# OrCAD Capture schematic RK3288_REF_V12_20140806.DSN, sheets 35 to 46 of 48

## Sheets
35 72.Audio Codec-ALC3224 (option): size A3; title: Audio Codec-ALC3224 (option); note: Audio Codec-ALC3224
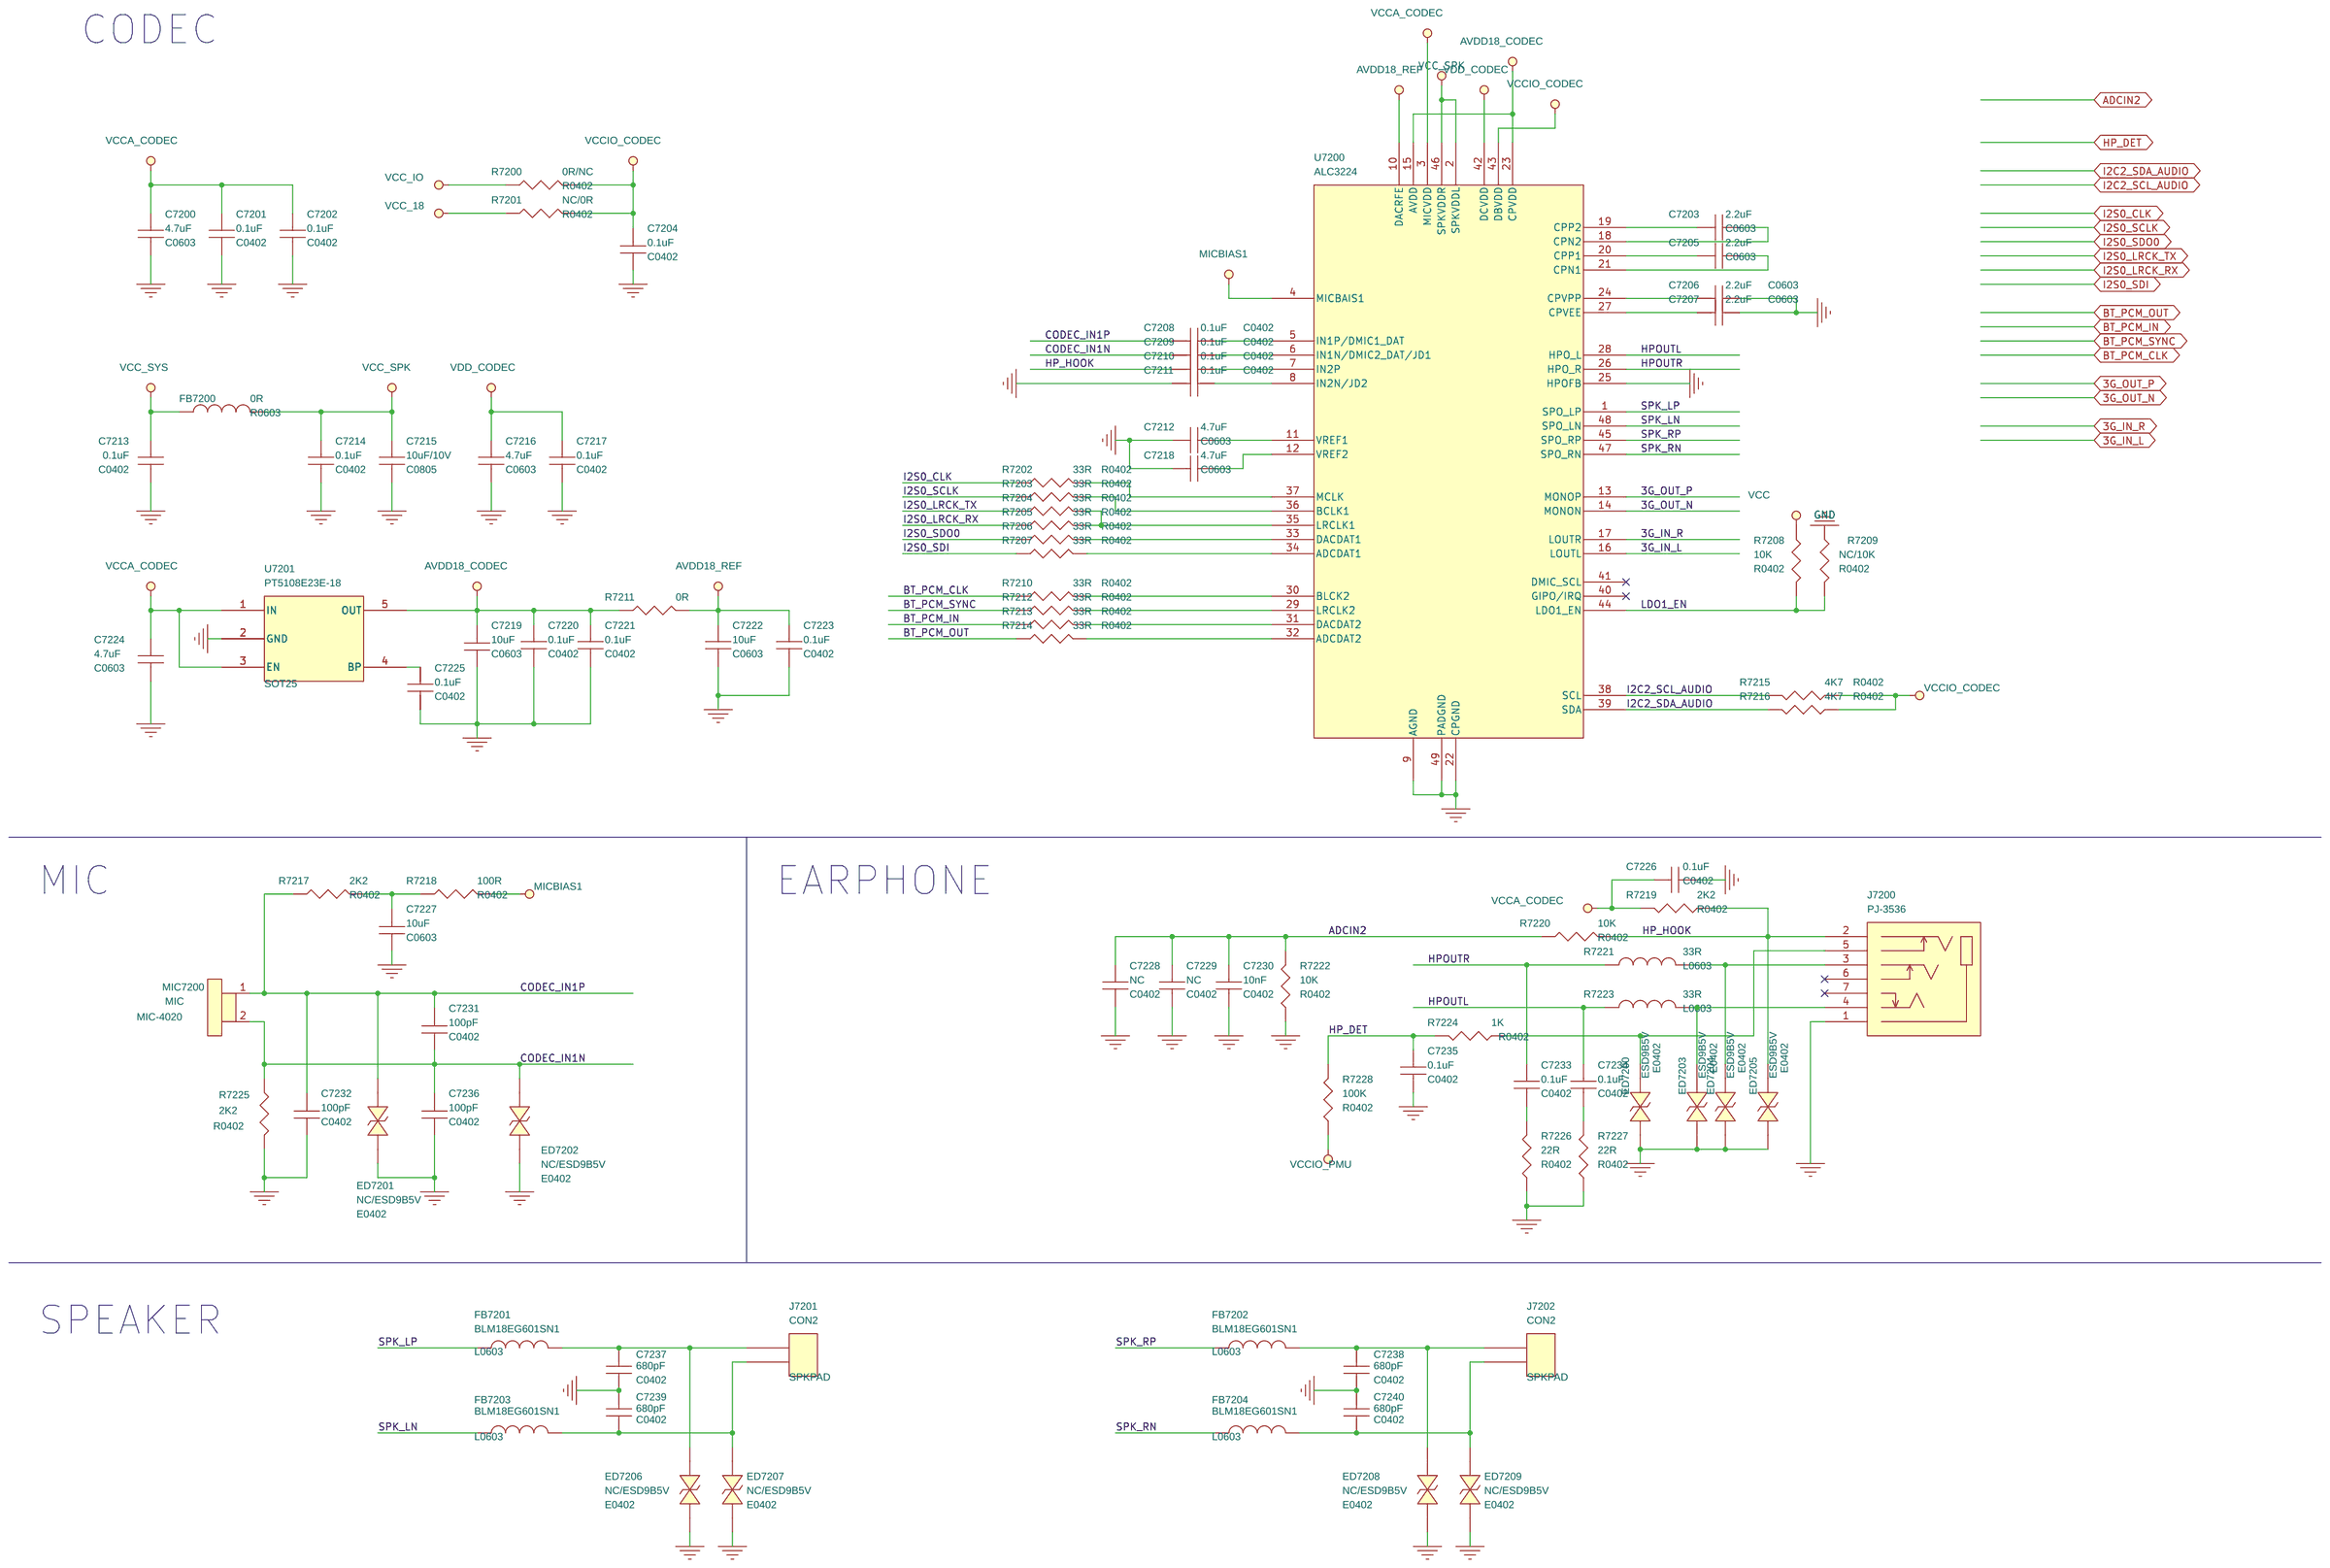
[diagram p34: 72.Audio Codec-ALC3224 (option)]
36 75.TP COF: size A4; title: TP COF; note: TP COF
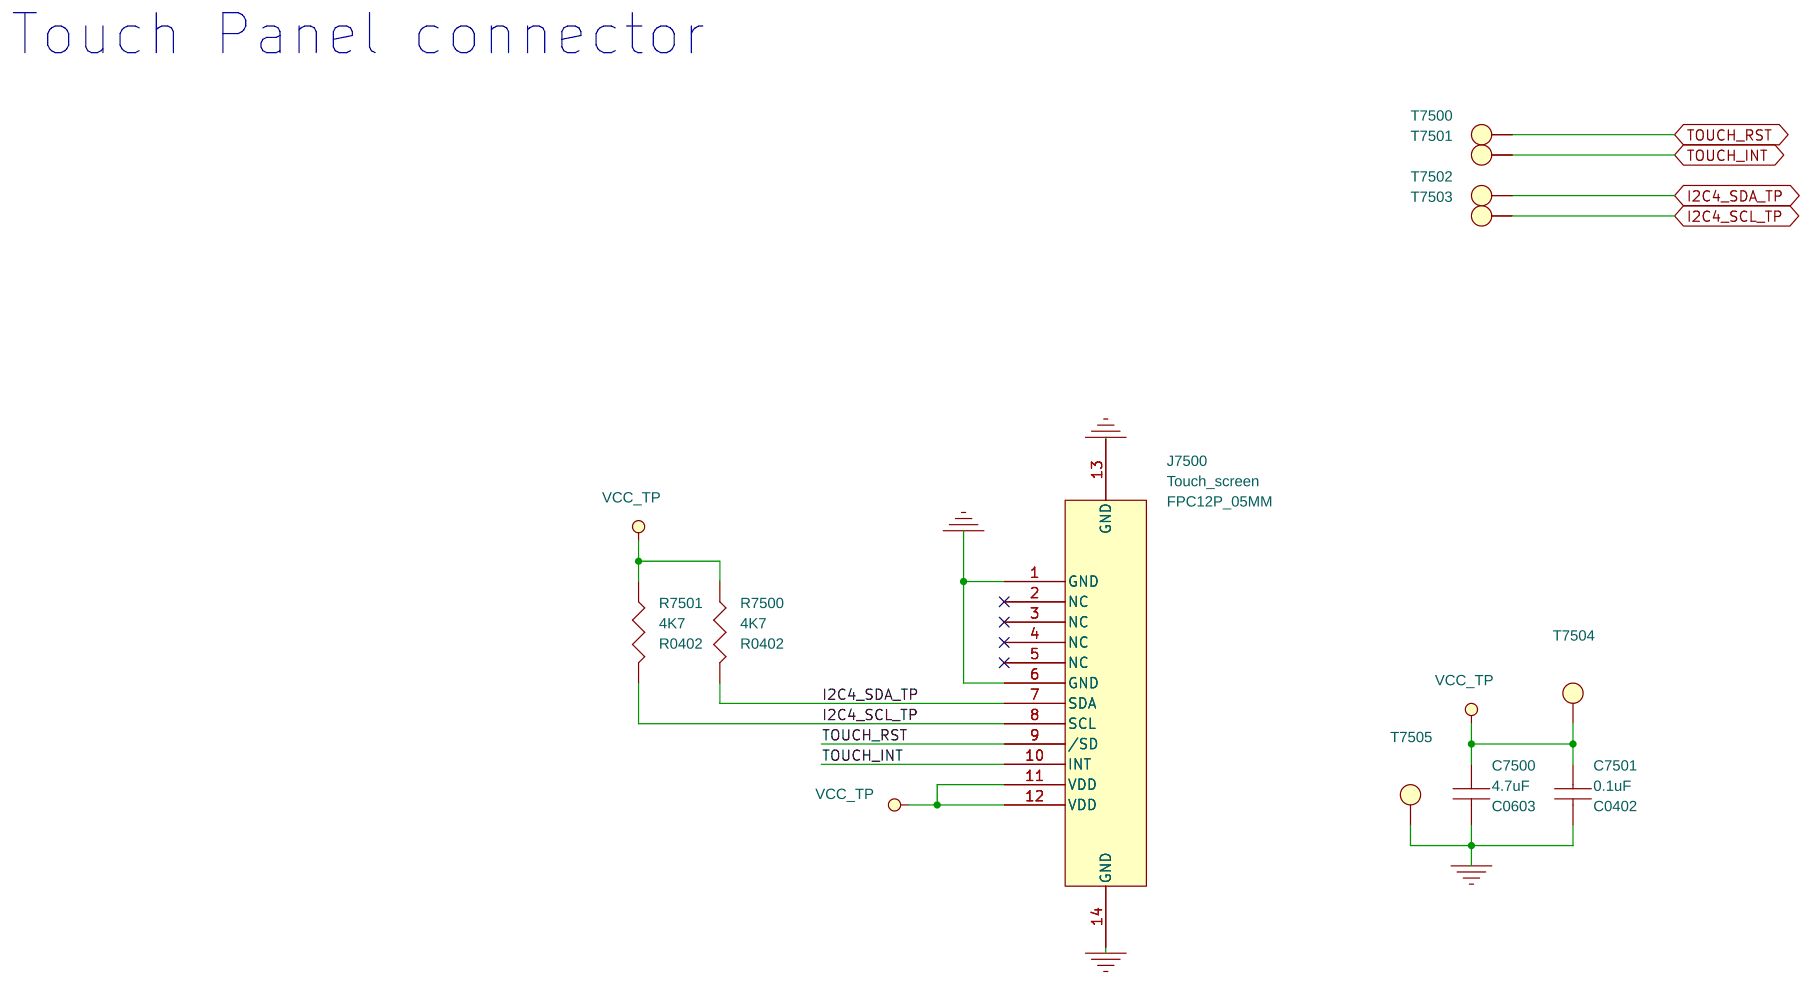
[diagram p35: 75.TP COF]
37 76.TP COB-CT363 (option): size A4; title: TP COB-CT363 (option); note: TP COB-CT363 (option)
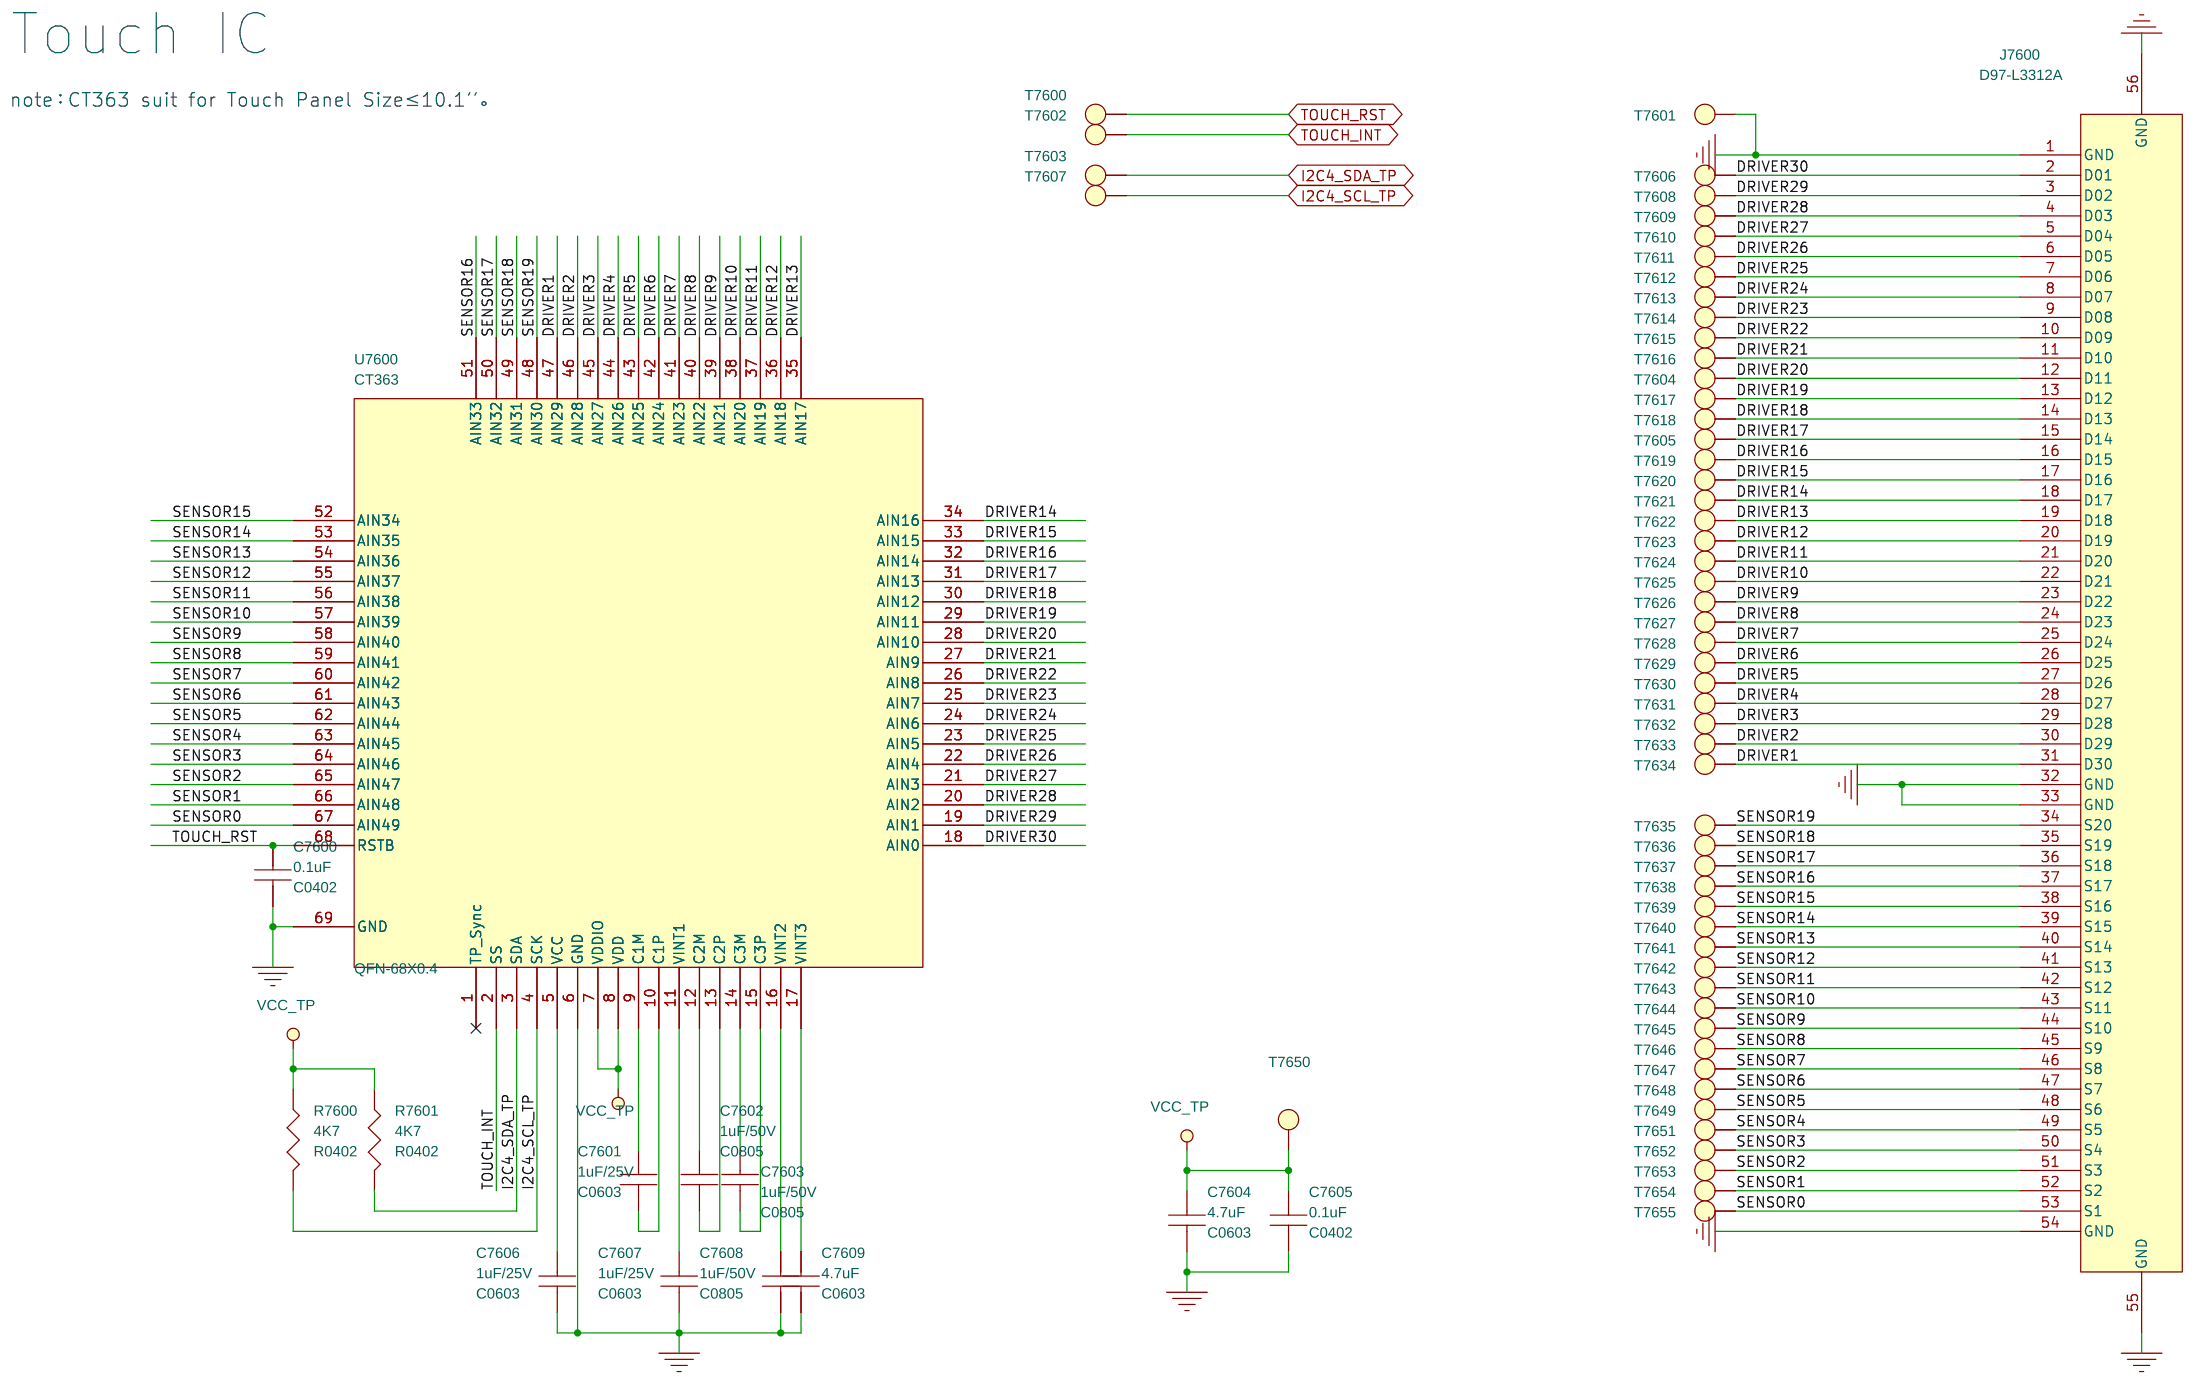
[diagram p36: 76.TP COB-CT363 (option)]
38 77.TP COB-FT5506 (option): size A4; title: TP COB-FT5506 (option); note: TP COB-FT5506 (option)
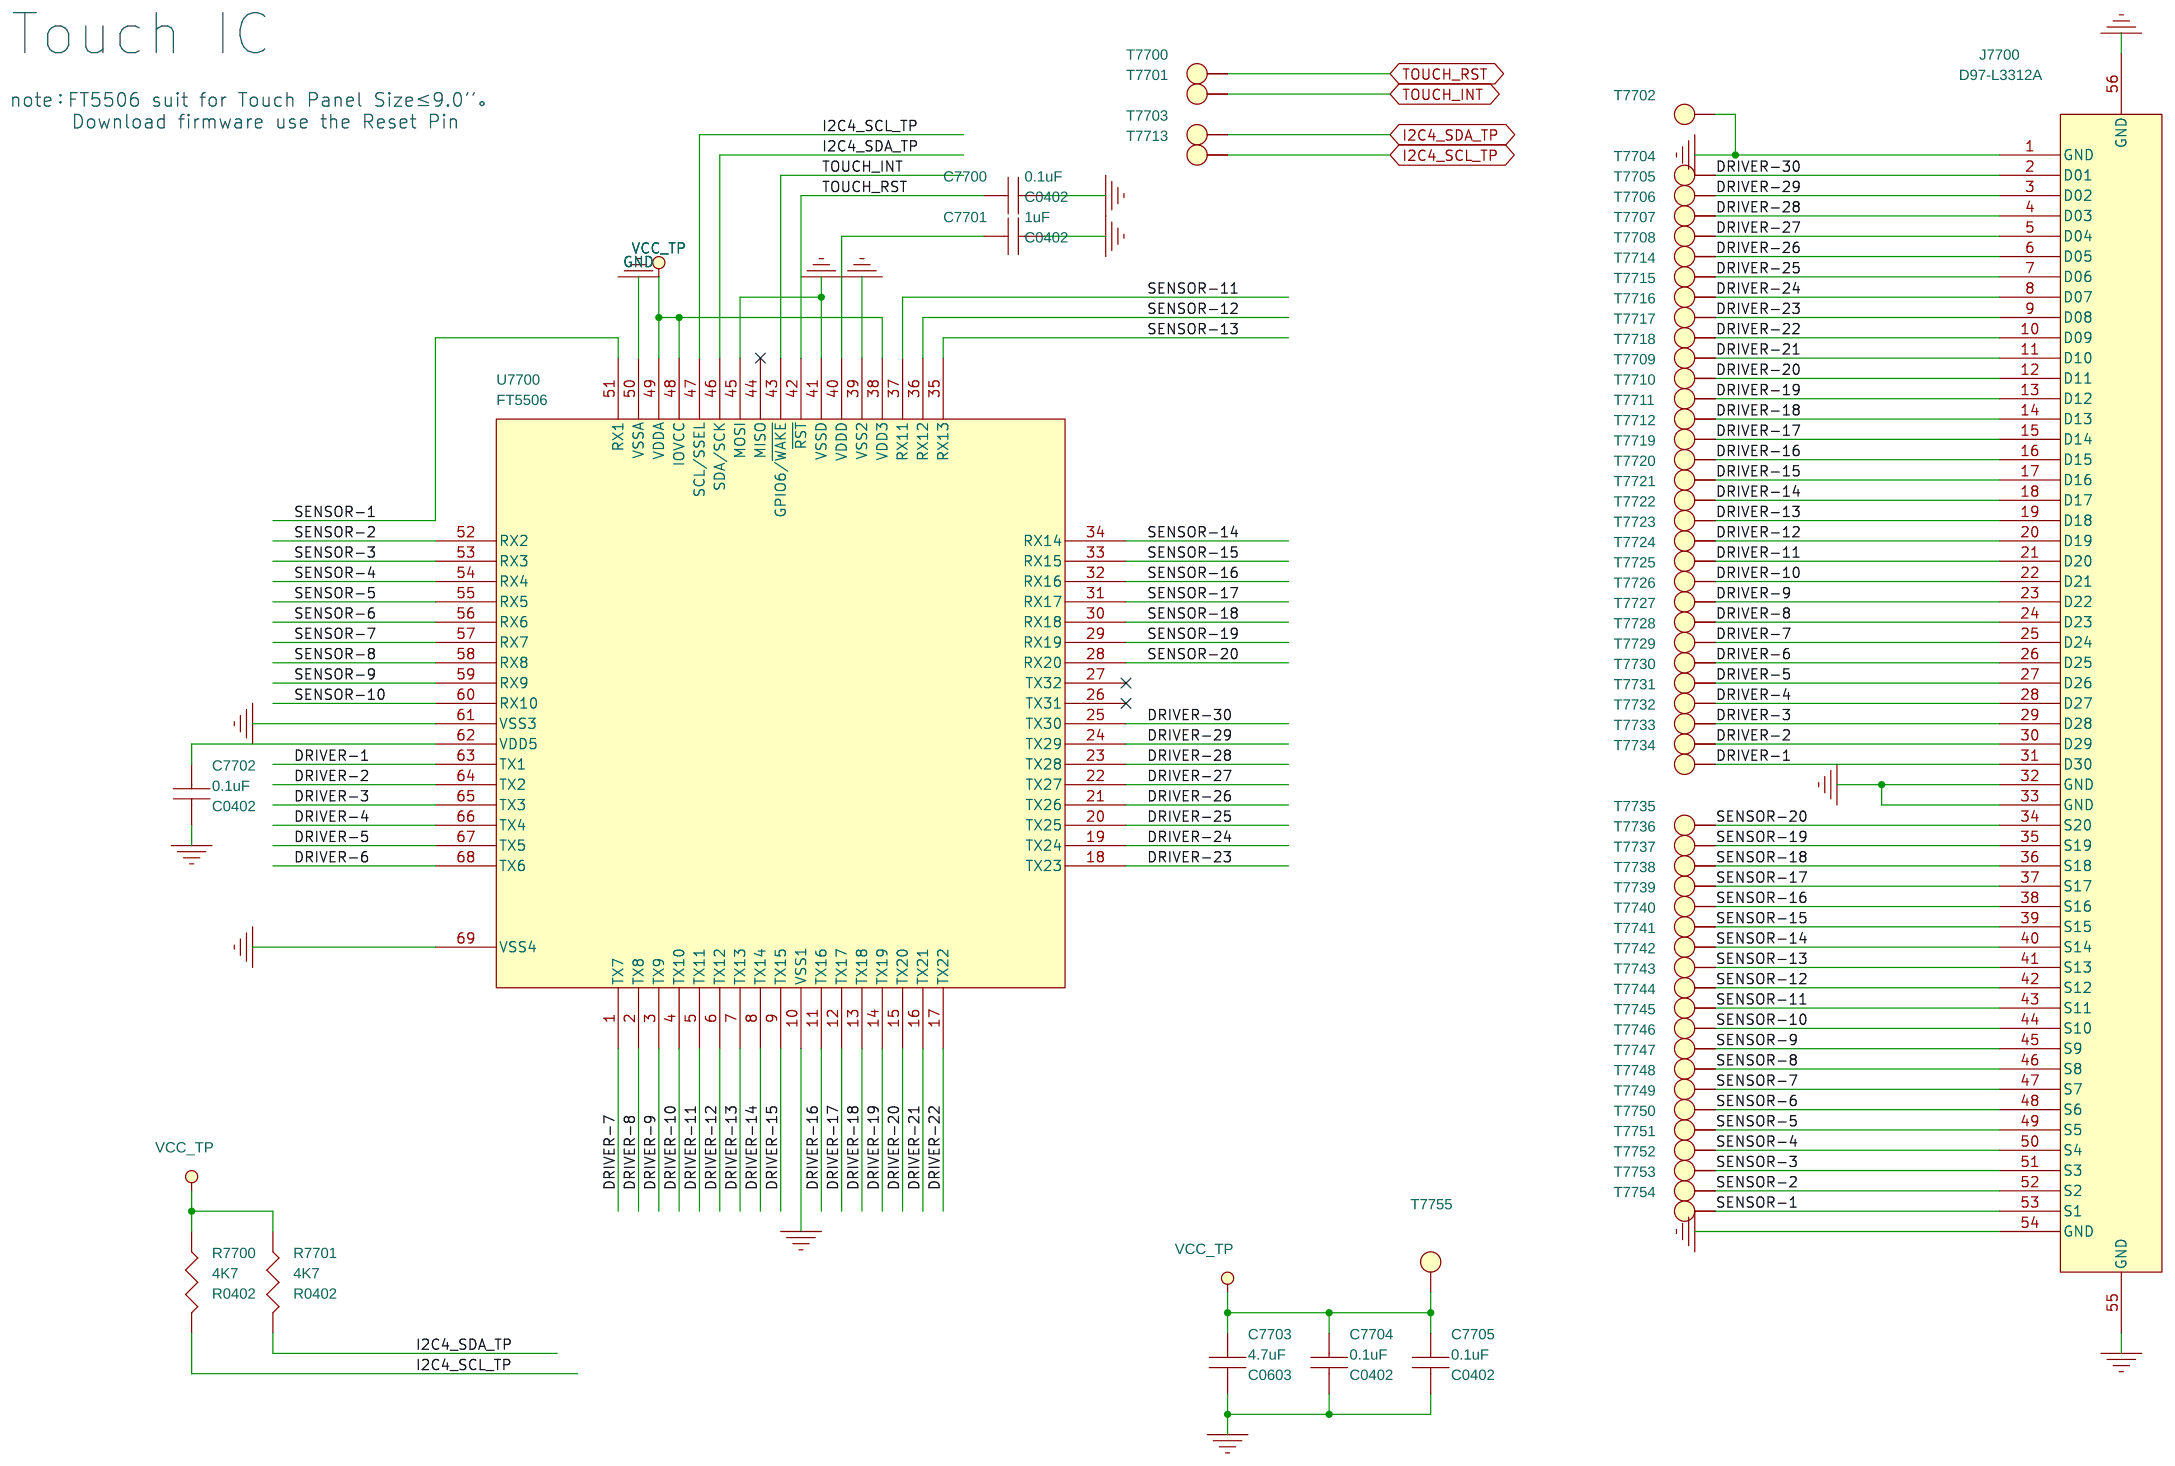
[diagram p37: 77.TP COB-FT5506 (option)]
39 78.TP COB-GSL3680 (option): size A4; title: TP COB-GSL3680 (option); note: TP COB-GSL3680 (option)
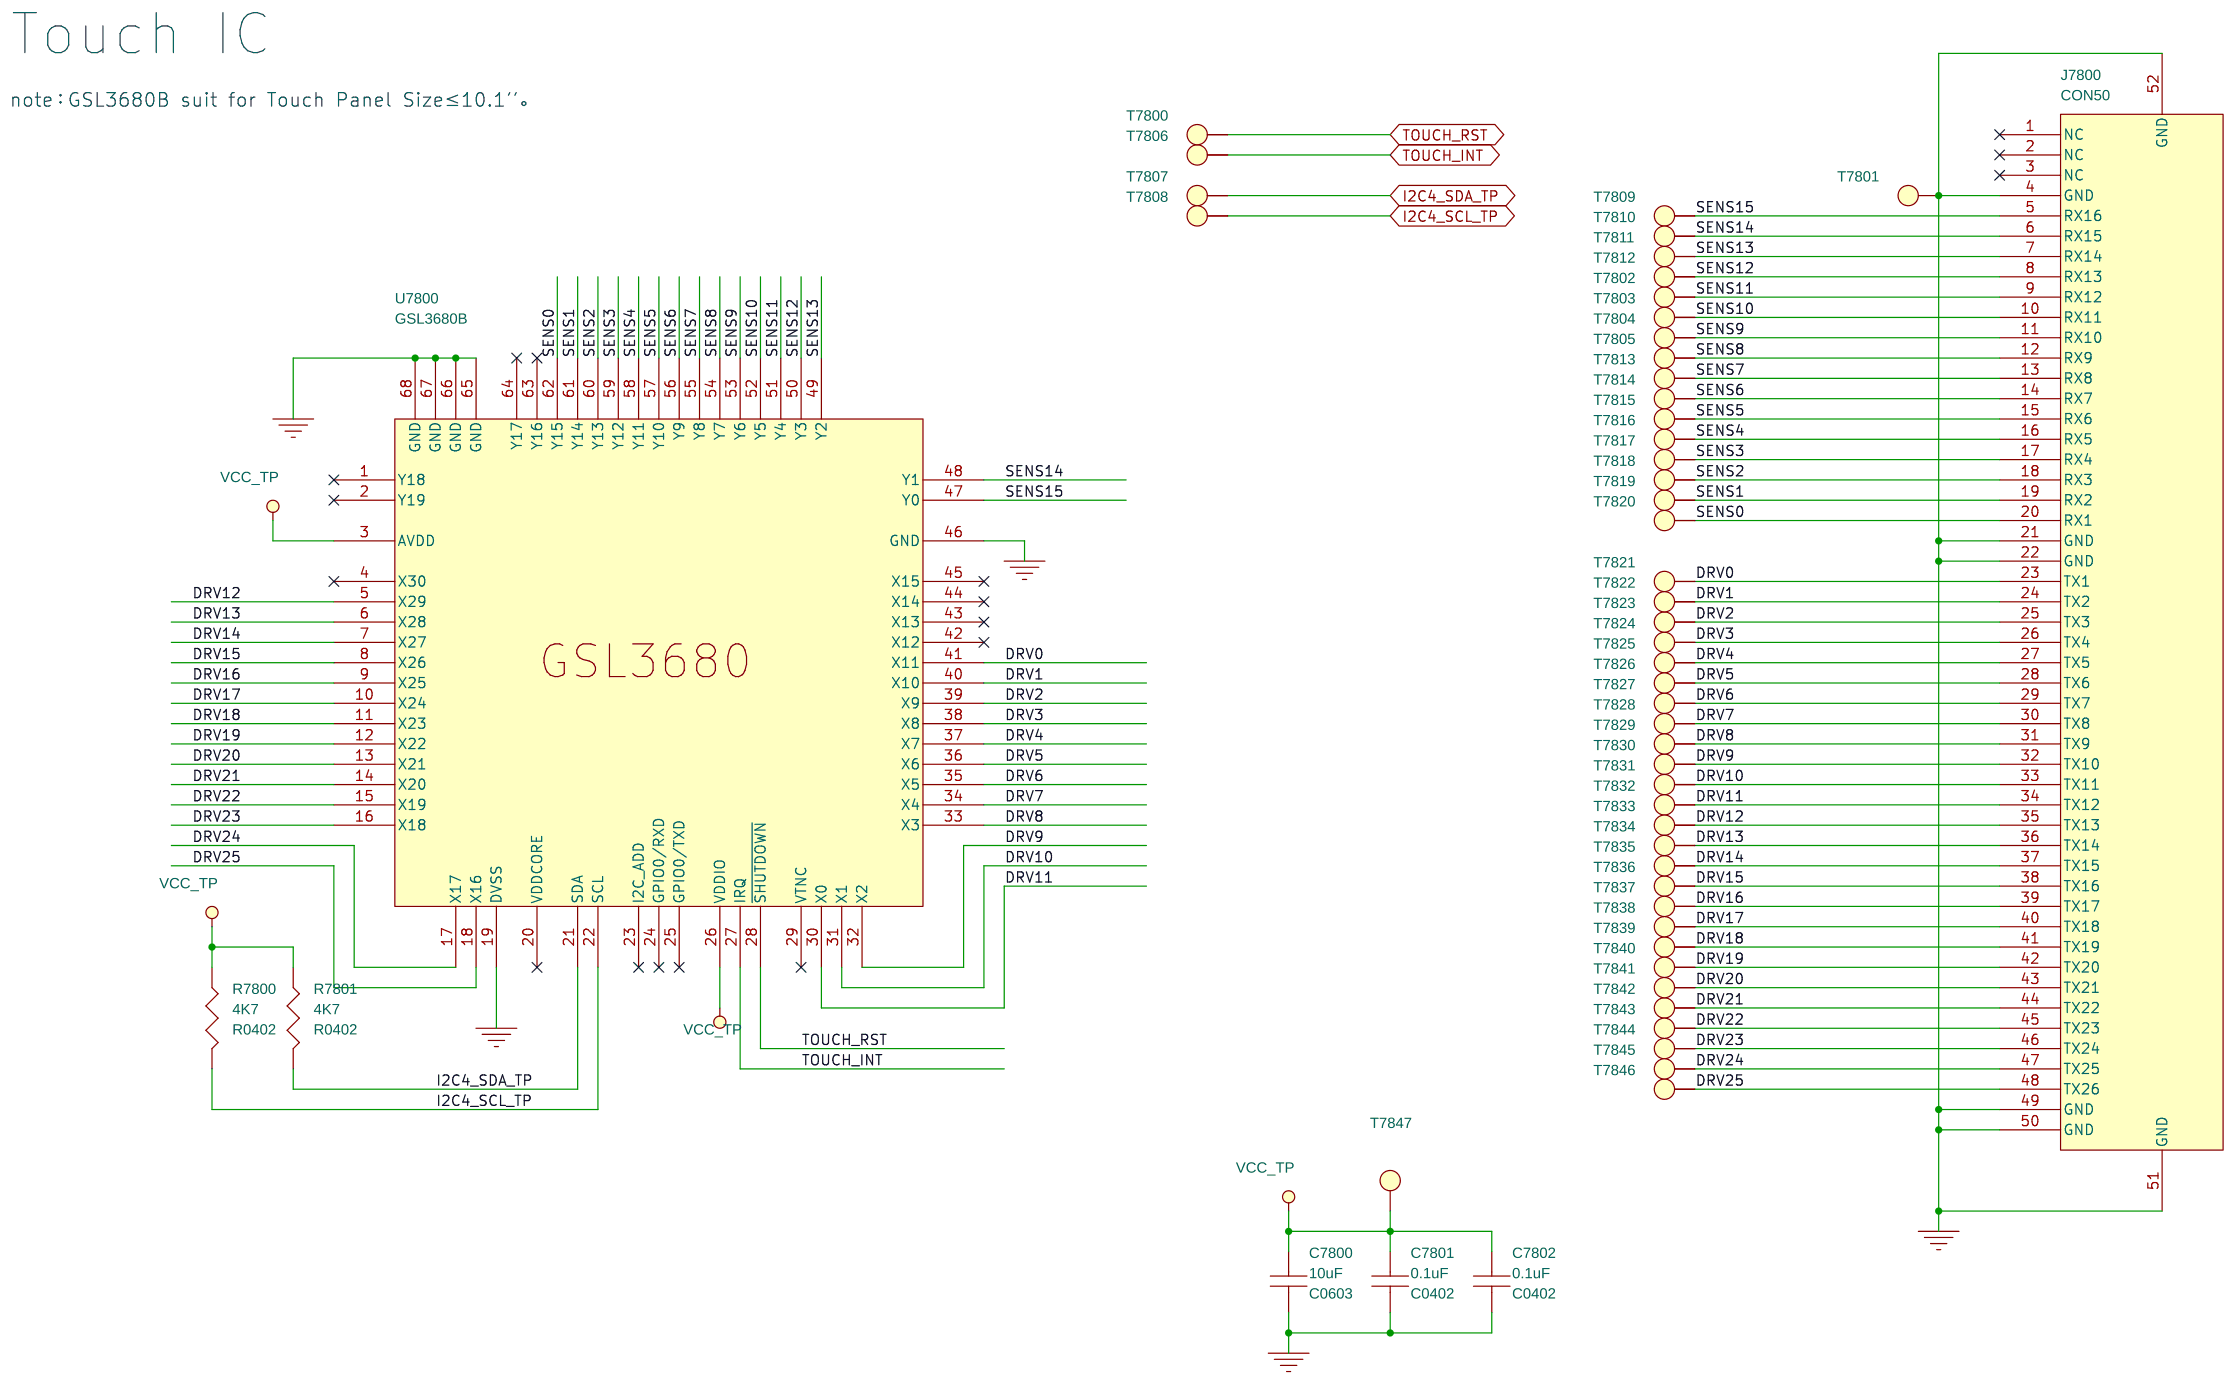
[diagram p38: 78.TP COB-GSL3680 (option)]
40 81.TF Card: size A4; title: TF Card; note: TF Card
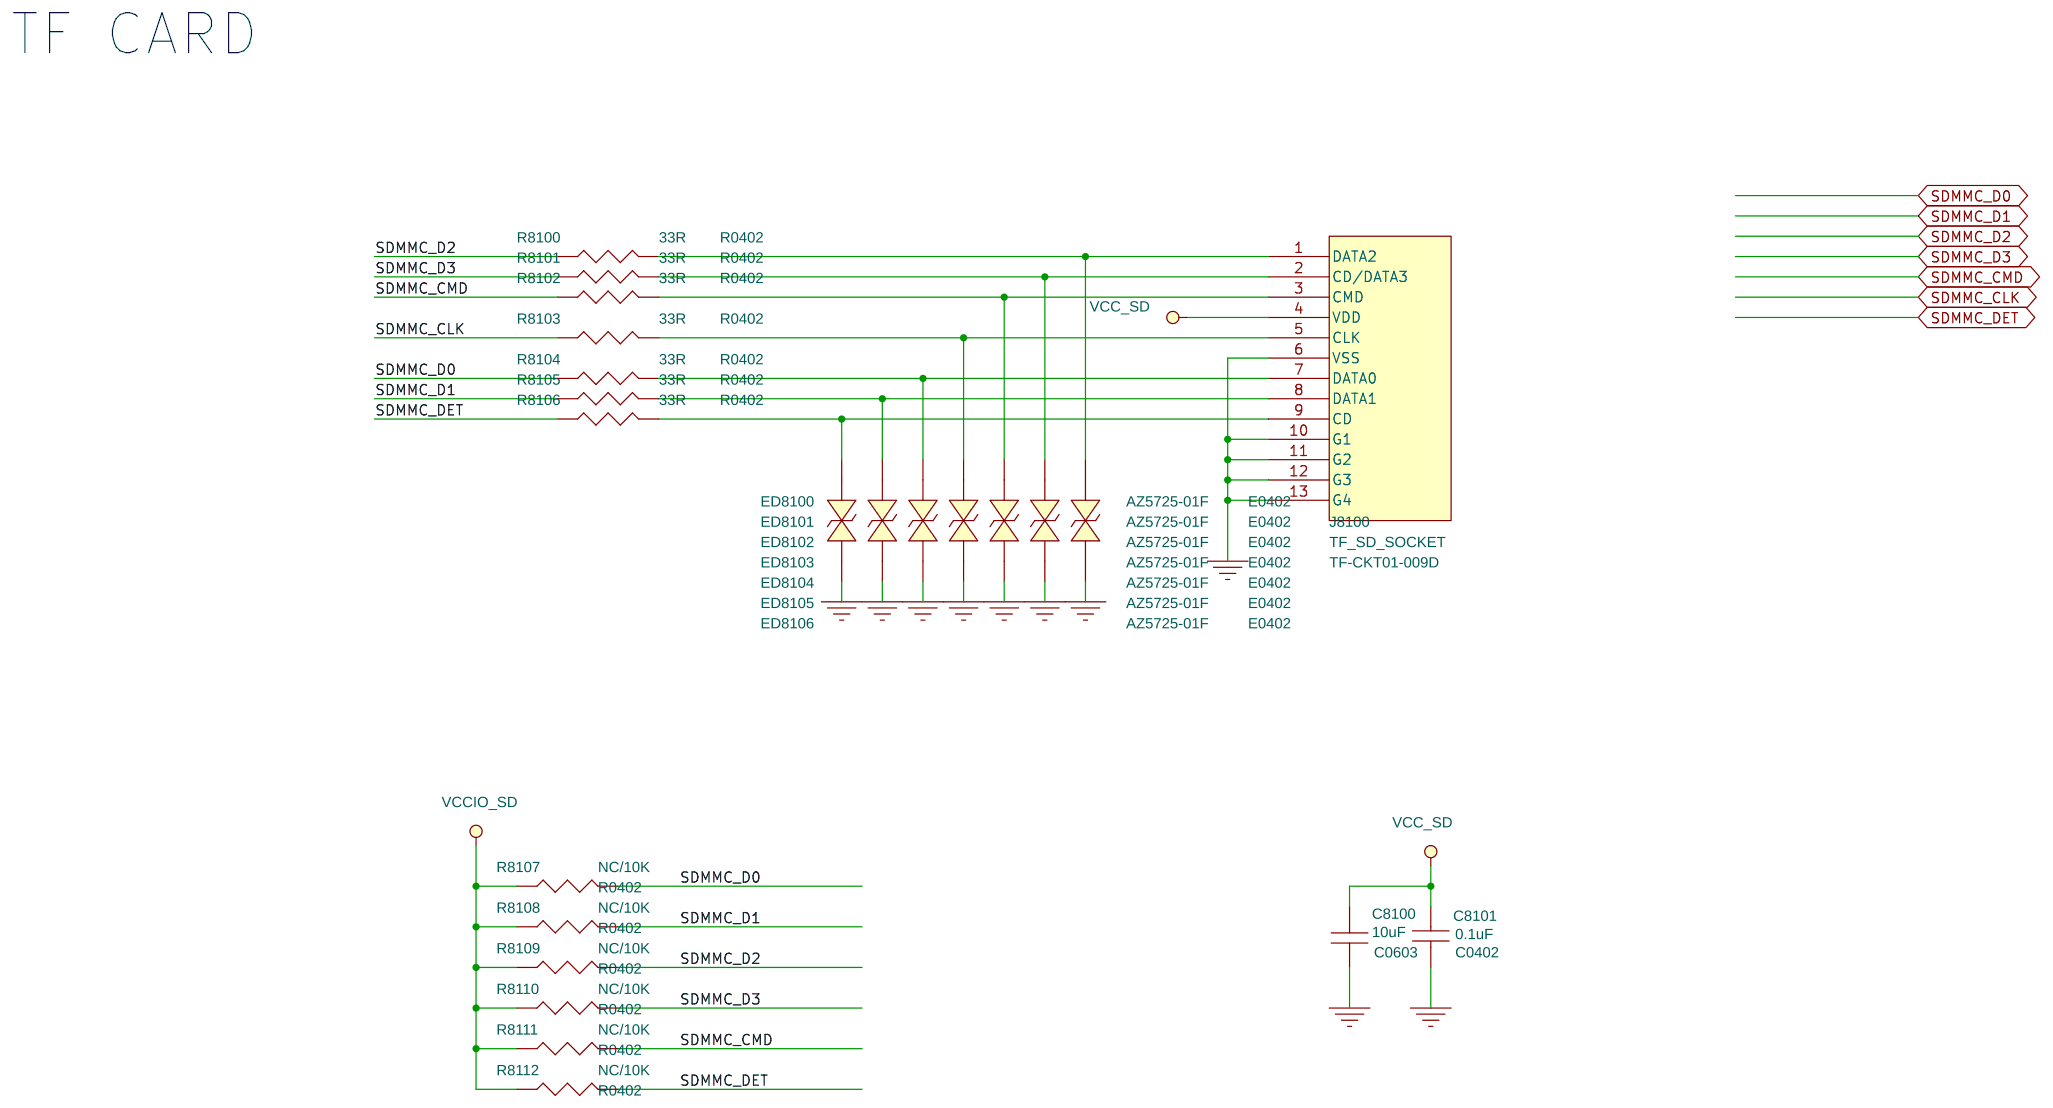
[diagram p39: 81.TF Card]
41 82.HDMI: size A4; title: HDMI Port; note: HDMI Port
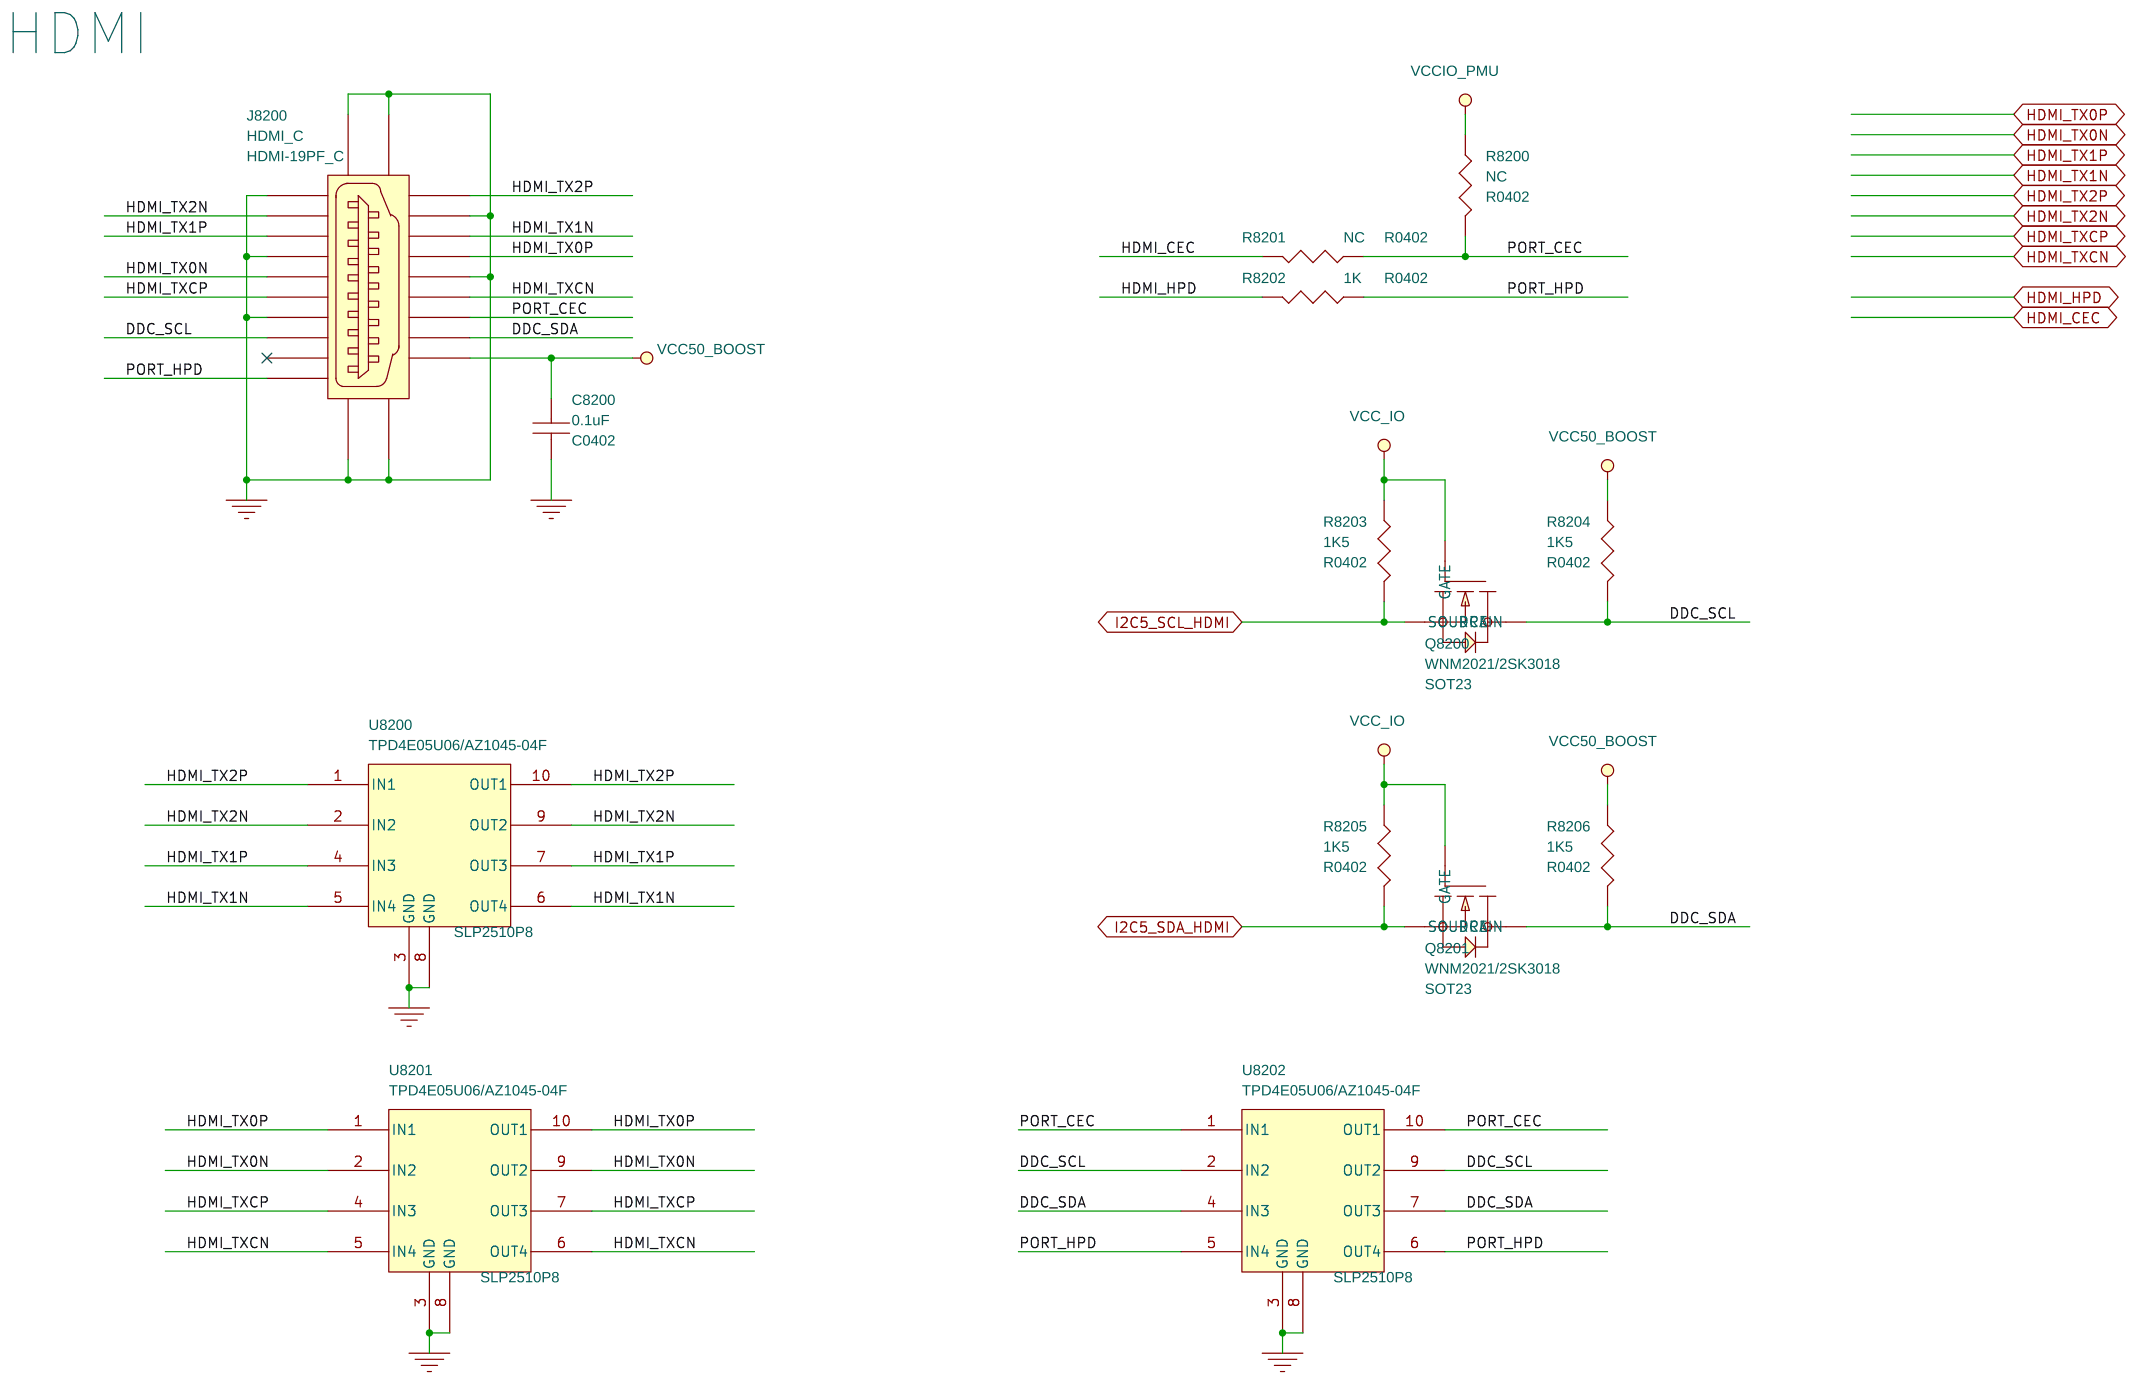
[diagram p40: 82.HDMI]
42 84.eFUSE (option): size A4; title: eFUSE (option); note: eFUSE (option)
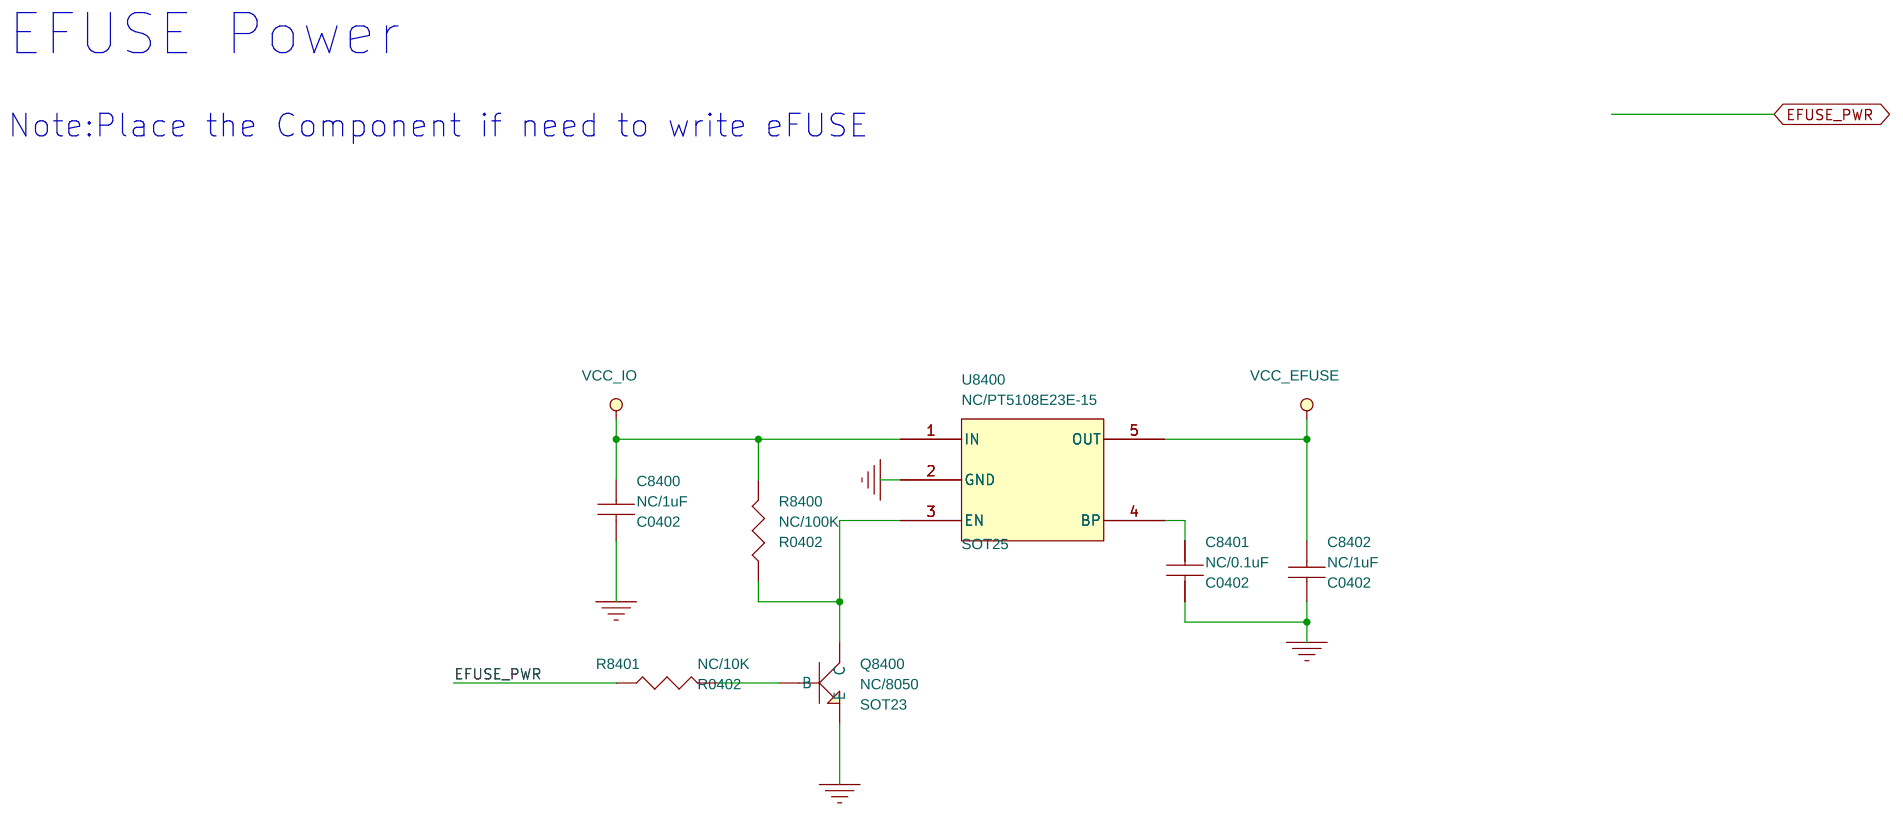
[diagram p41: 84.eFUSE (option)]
43 80.Sensor/VIB: size A3; title: Sensor/VIB; note: Sensor/VIB
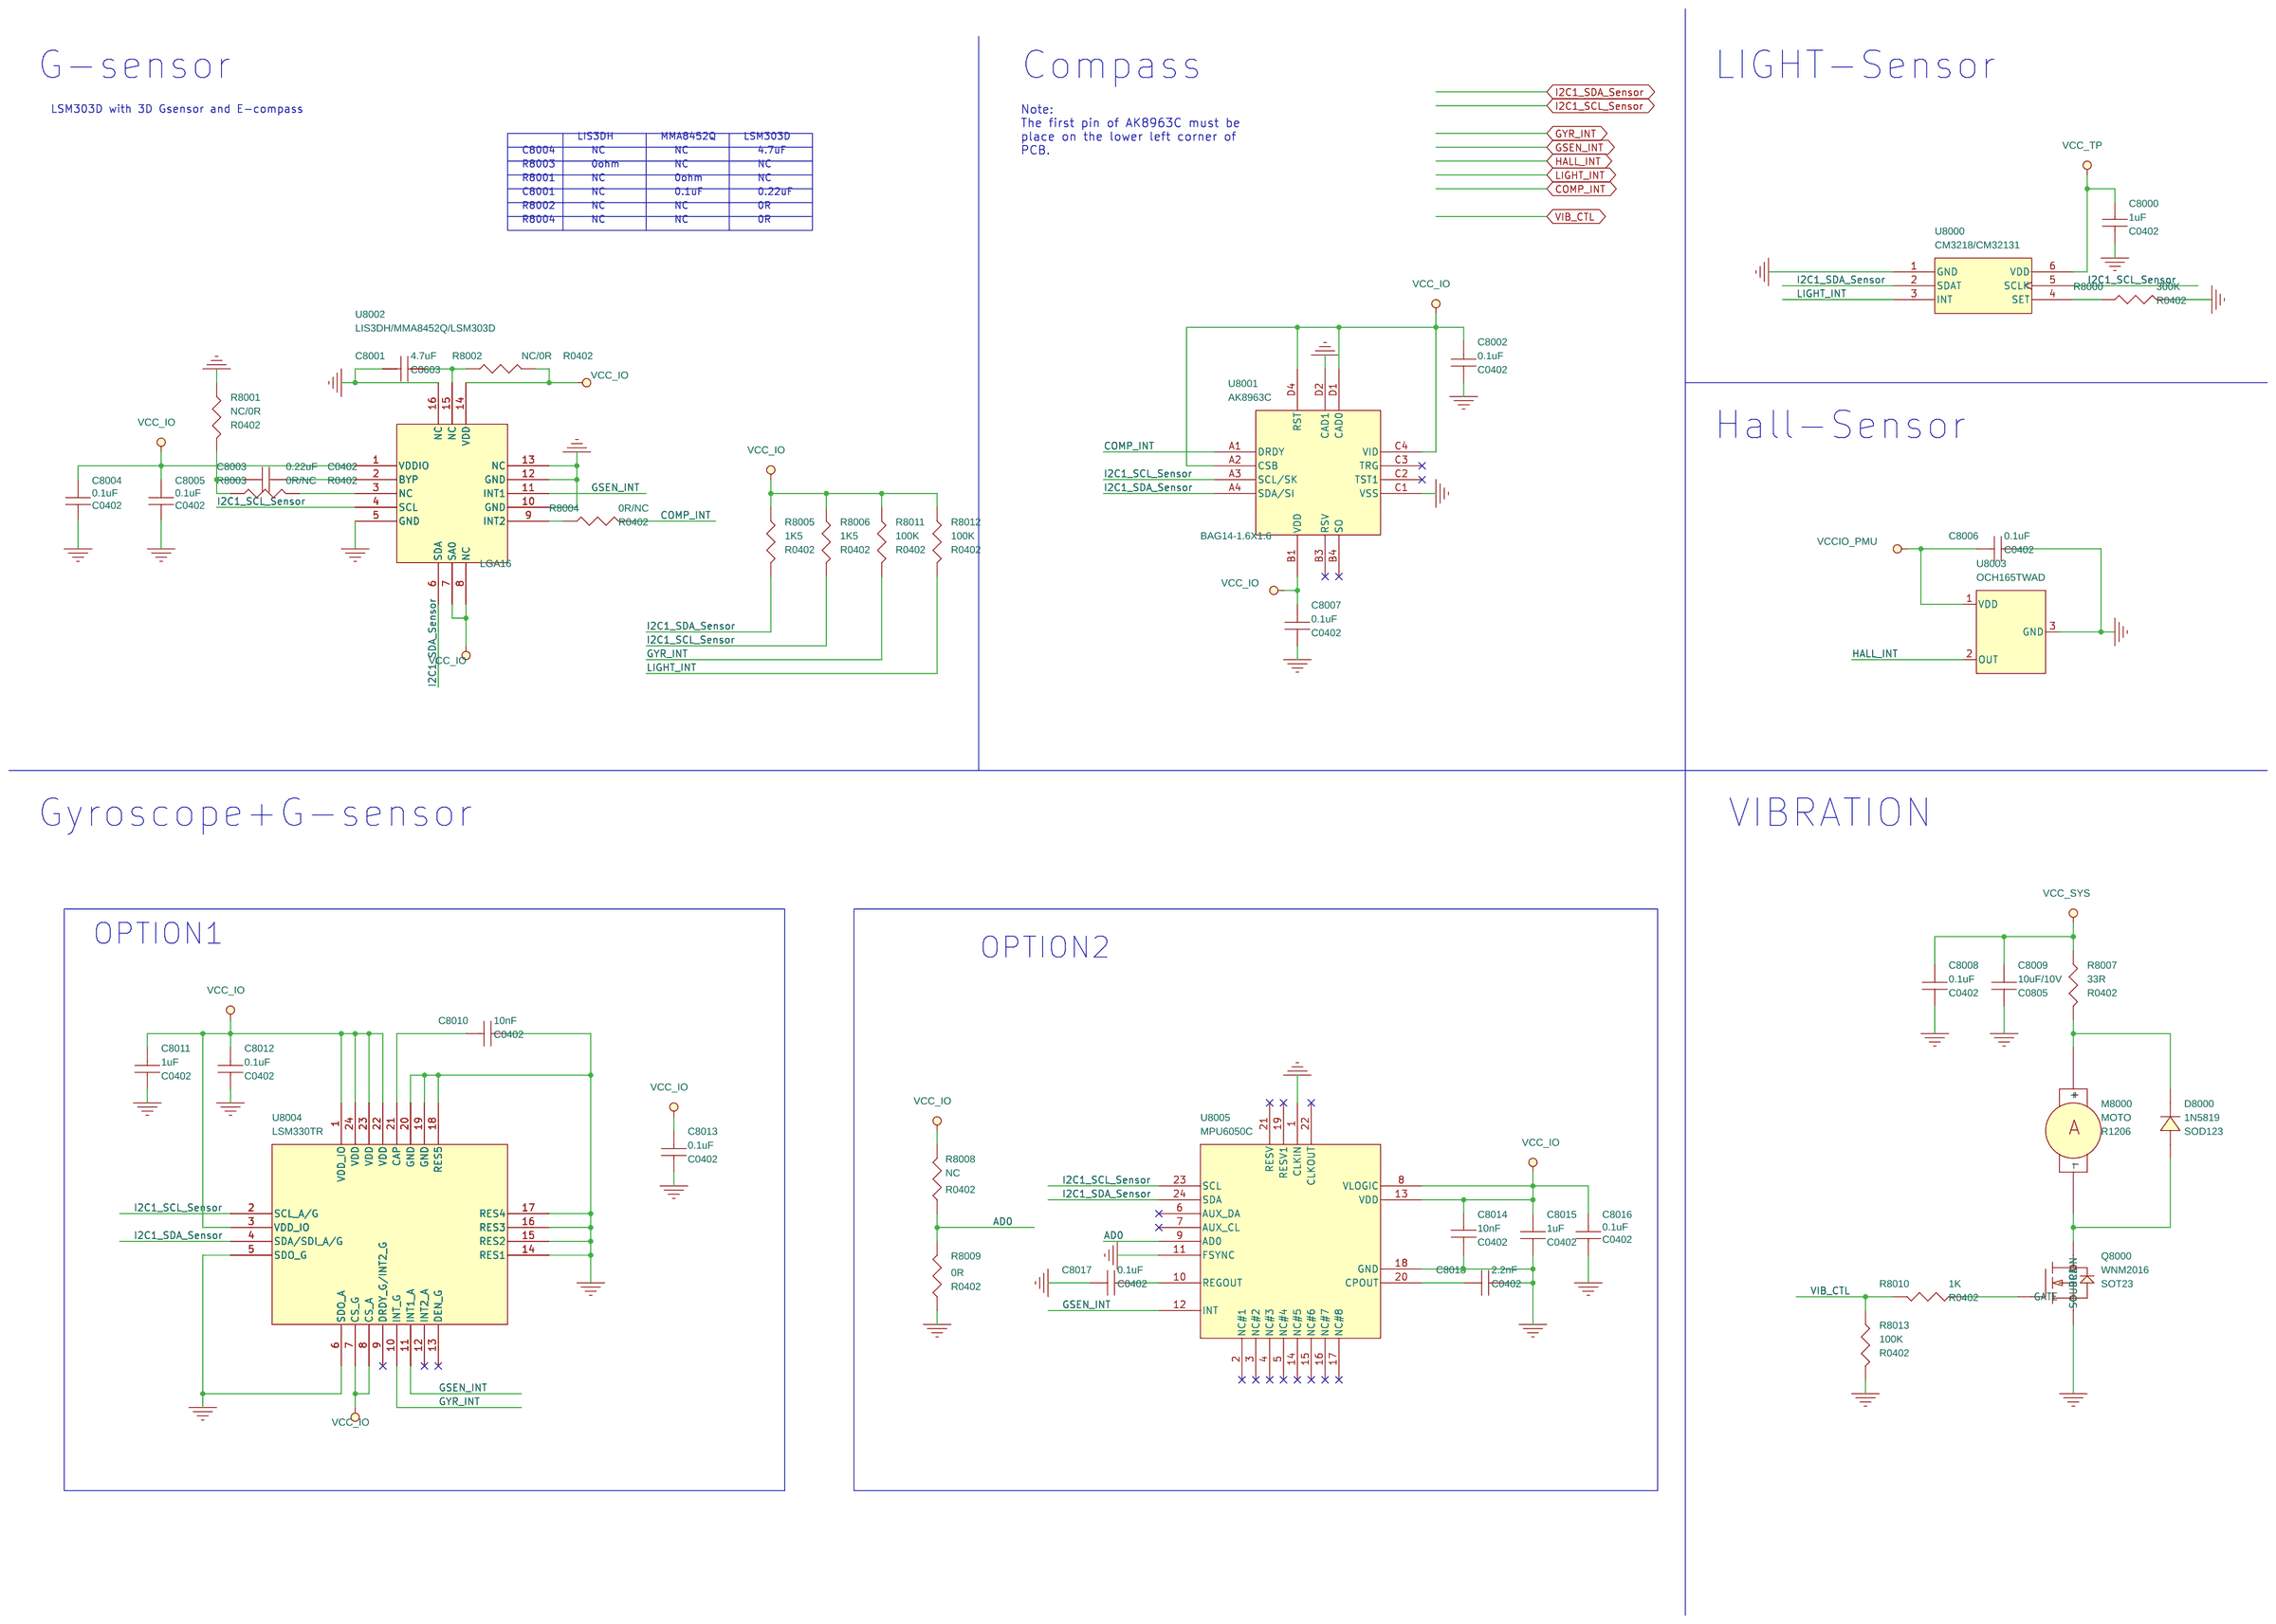
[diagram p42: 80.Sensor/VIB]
44 60.WIFI/BT-AP6210: size A4; title: WIFI/BT-AP6210; note: WIFI/BT-AP6210
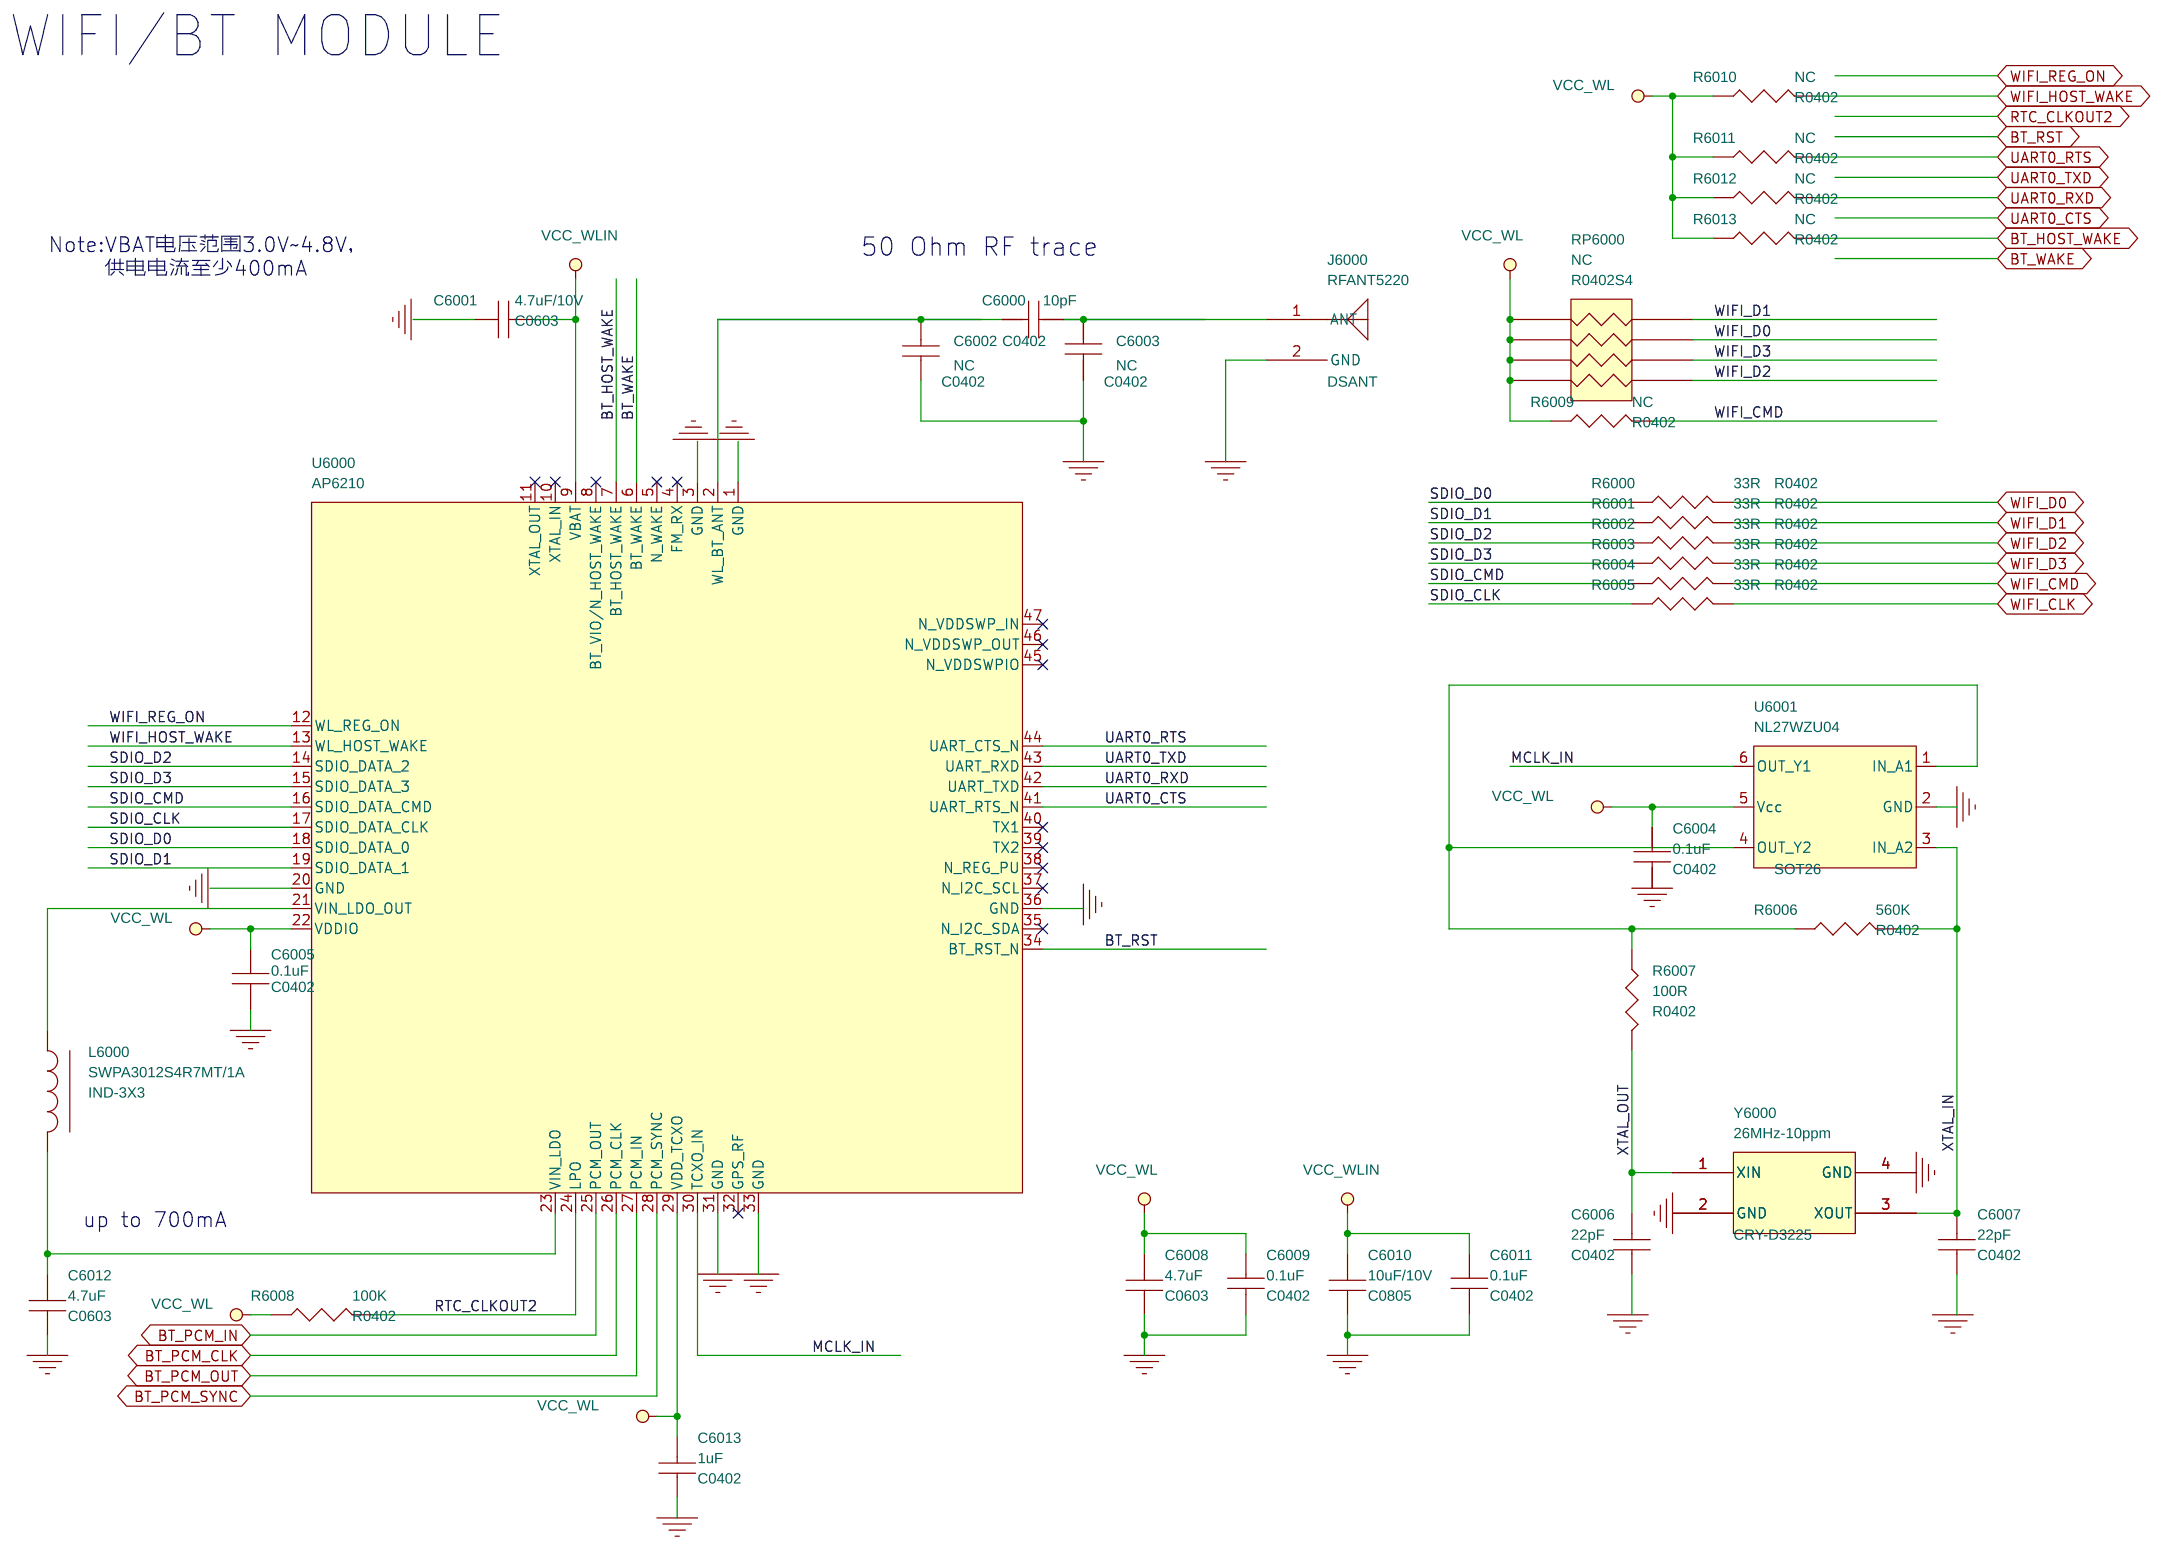
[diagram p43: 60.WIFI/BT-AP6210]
45 15.RK3288 SARADC/Key Board: size A4; title: RK3288 SARADC/Key Board; note: RK3288 SARADC/Key Board
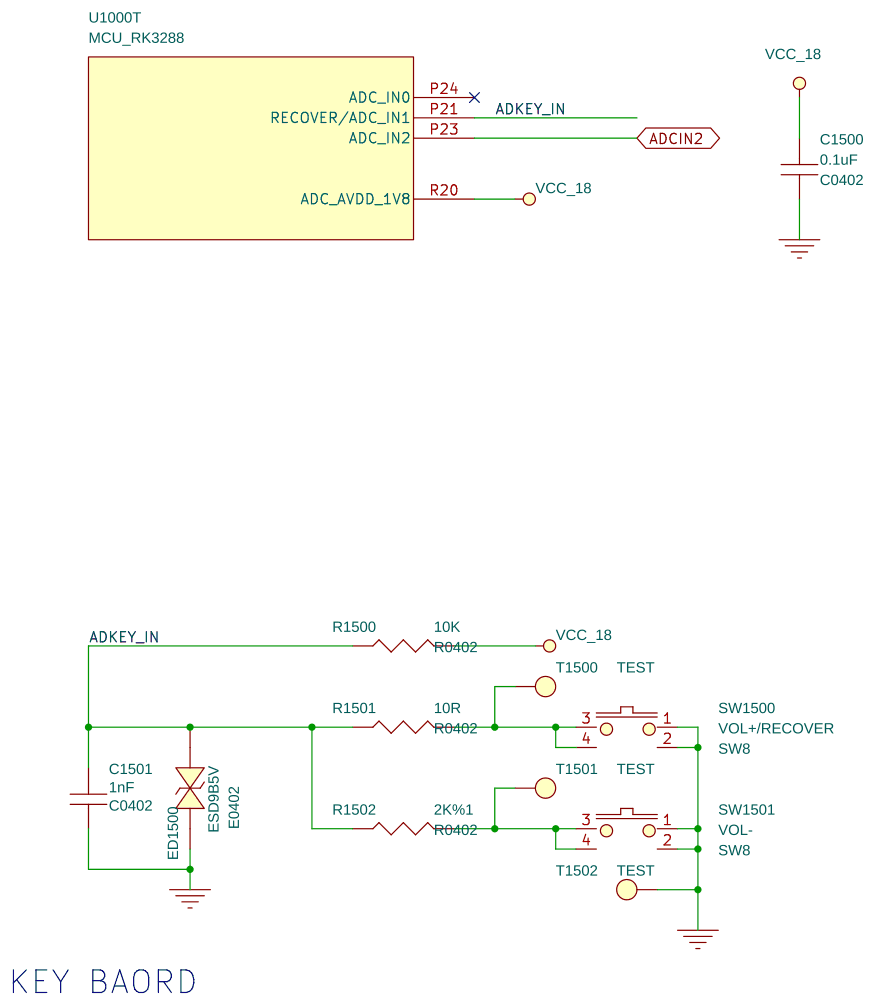
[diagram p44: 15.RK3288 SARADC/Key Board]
46 14.RK3288 USB/HSIC Controler: size A4; title: RK3288 USB/HSIC Controler; note: RK3288 USB/HSIC Controler
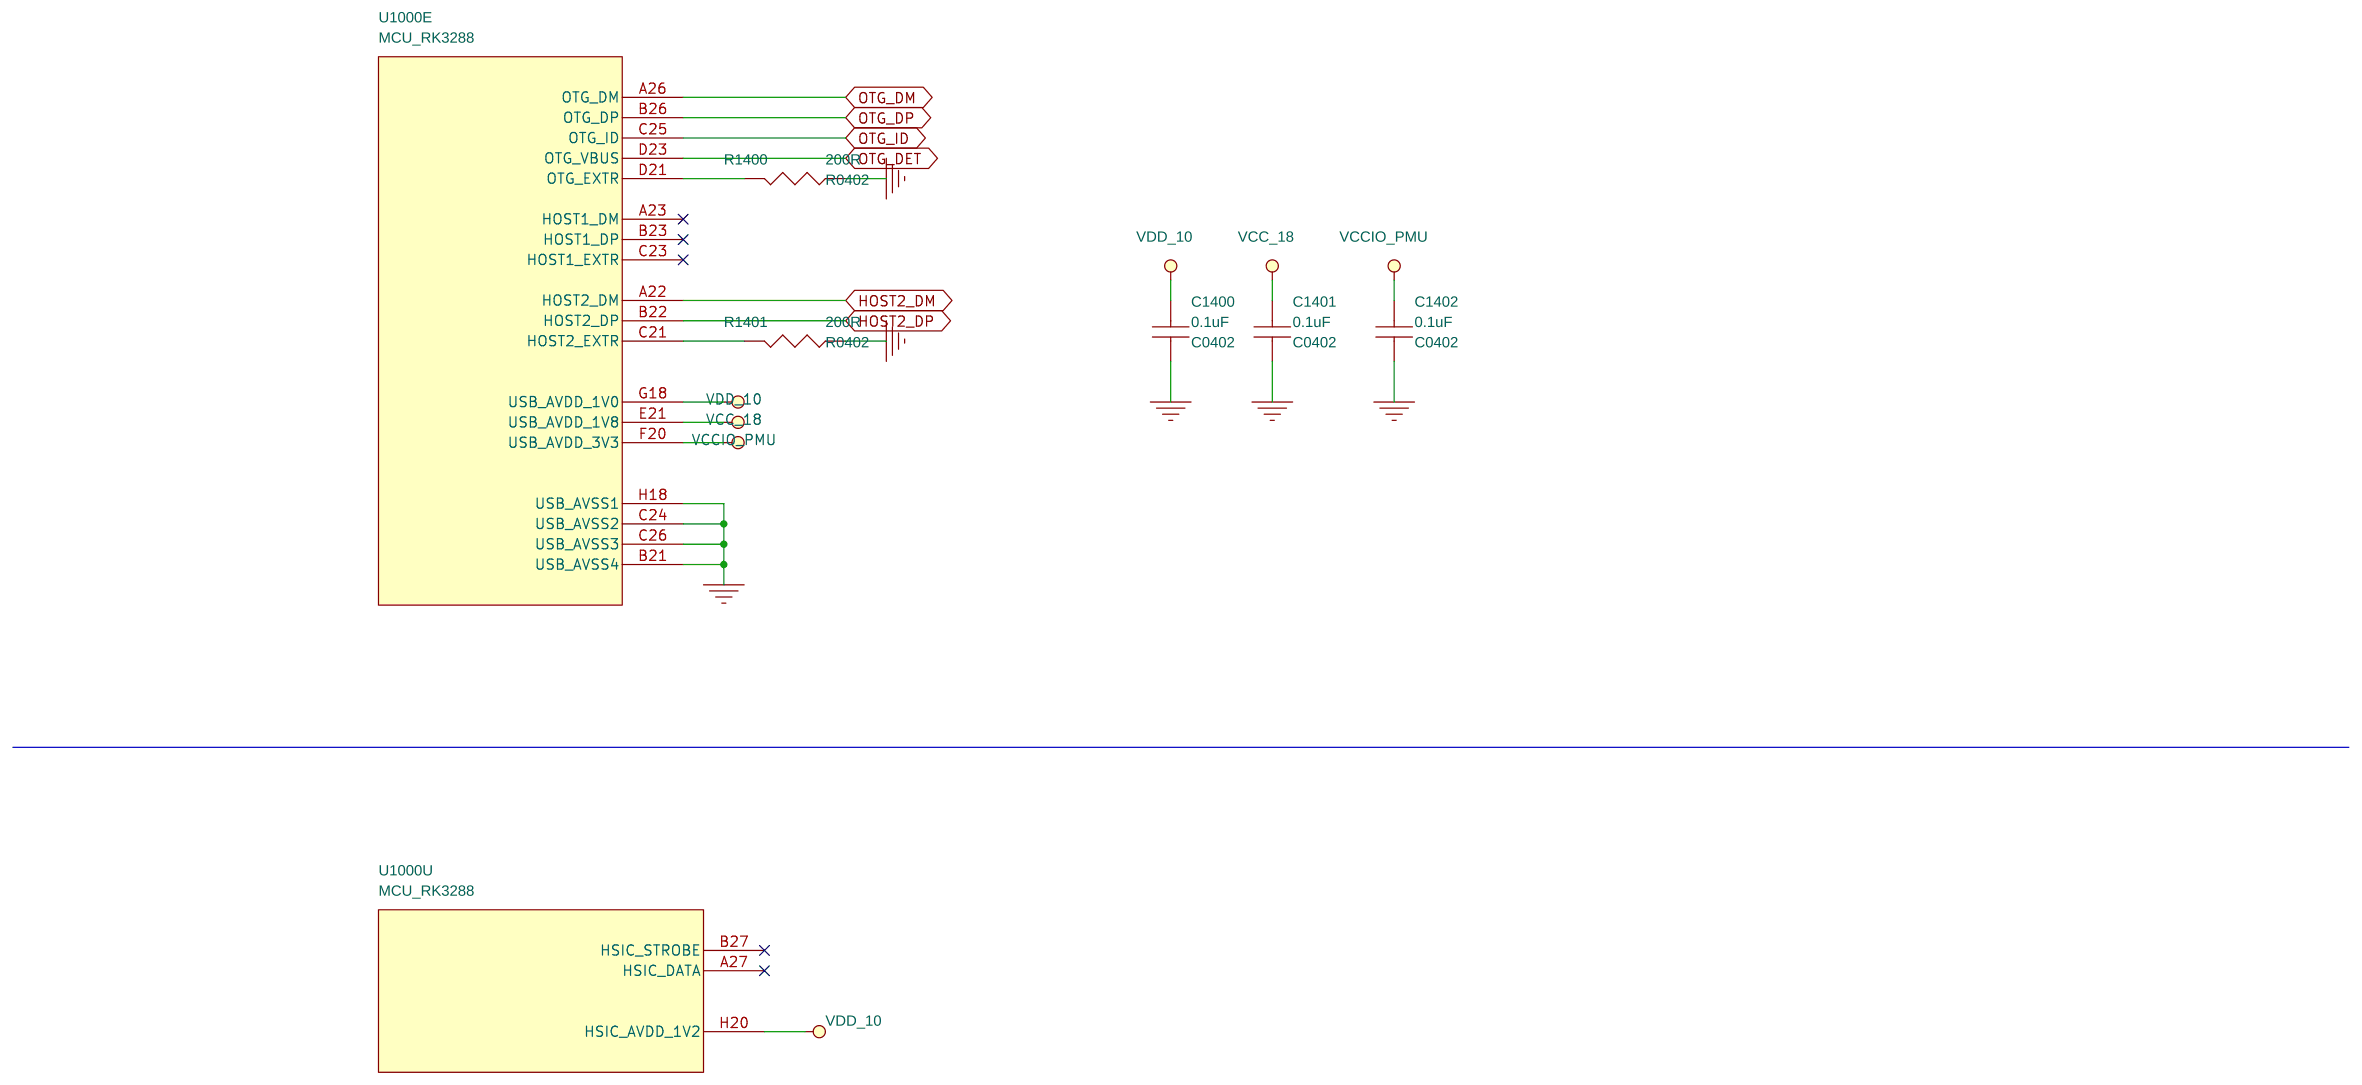
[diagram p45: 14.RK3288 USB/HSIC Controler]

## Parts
sheet 13.RK3288 Flash Controler
U1000  MCU_RK3288  [BGA636_19x19]  (sections A,B,C,D,E,F,G,H,I,J,K,L,M,N,O,P,Q,R,T,U,V,W,X)
sheet 14.RK3288 USB/HSIC Controler
C1400  0.1uF  [C0402]
C1401  0.1uF  [C0402]
C1402  0.1uF  [C0402]
R1400  200R  [R0402]
R1401  200R  [R0402]
sheet 15.RK3288 SARADC/Key Board
C1500  0.1uF  [C0402]
C1501  1nF  [C0402]
ED1500  ESD9B5V  [E0402]
R1500  10K  [R0402]
R1501  10R  [R0402]
R1502  2K%1  [R0402]
SW1500  VOL+/RECOVER  [SW8]
SW1501  VOL-  [SW8]
T1500  TEST  [T-0.7]
T1501  TEST  [T-0.7]
T1502  TEST  [T-0.7]
sheet 60.WIFI/BT-AP6210
C6000  10pF  [C0402]
C6001  4.7uF/10V  [C0603]
C6002  NC  [C0402]
C6003  NC  [C0402]
C6004  0.1uF  [C0402]
C6005  0.1uF  [C0402]
C6006  22pF  [C0402]
C6007  22pF  [C0402]
C6008  4.7uF  [C0603]
C6009  0.1uF  [C0402]
C6010  10uF/10V  [C0805]
C6011  0.1uF  [C0402]
C6012  4.7uF  [C0603]
C6013  1uF  [C0402]
J6000  RFANT5220  [DSANT]
L6000  SWPA3012S4R7MT/1A  [IND-3X3]
R6000  33R  [R0402]
R6001  33R  [R0402]
R6002  33R  [R0402]
R6003  33R  [R0402]
R6004  33R  [R0402]
R6005  33R  [R0402]
R6006  560K  [R0402]
R6007  100R  [R0402]
R6008  100K  [R0402]
R6009  NC  [R0402]
R6010  NC  [R0402]
R6011  NC  [R0402]
R6012  NC  [R0402]
R6013  NC  [R0402]
RP6000  NC  [R0402S4]
U6000  AP6210  [AP6XXX]
U6001  NL27WZU04  [SOT26]
Y6000  26MHz-10ppm  [CRY-D3225]
sheet 72.Audio Codec-ALC3224 (option)
C7200  4.7uF  [C0603]
C7201  0.1uF  [C0402]
C7202  0.1uF  [C0402]
C7203  2.2uF  [C0603]
C7204  0.1uF  [C0402]
C7205  2.2uF  [C0603]
C7206  2.2uF  [C0603]
C7207  2.2uF  [C0603]
C7208  0.1uF  [C0402]
C7209  0.1uF  [C0402]
C7210  0.1uF  [C0402]
C7211  0.1uF  [C0402]
C7212  4.7uF  [C0603]
C7213  0.1uF  [C0402]
C7214  0.1uF  [C0402]
C7215  10uF/10V  [C0805]
C7216  4.7uF  [C0603]
C7217  0.1uF  [C0402]
C7218  4.7uF  [C0603]
C7219  10uF  [C0603]
C7220  0.1uF  [C0402]
C7221  0.1uF  [C0402]
C7222  10uF  [C0603]
C7223  0.1uF  [C0402]
C7224  4.7uF  [C0603]
C7225  0.1uF  [C0402]
C7226  0.1uF  [C0402]
C7227  10uF  [C0603]
C7228  NC  [C0402]
C7229  NC  [C0402]
C7230  10nF  [C0402]
C7231  100pF  [C0402]
C7232  100pF  [C0402]
C7233  0.1uF  [C0402]
C7234  0.1uF  [C0402]
C7235  0.1uF  [C0402]
C7236  100pF  [C0402]
C7237  680pF  [C0402]
C7238  680pF  [C0402]
C7239  680pF  [C0402]
C7240  680pF  [C0402]
ED7200  ESD9B5V  [E0402]
ED7201  NC/ESD9B5V  [E0402]
ED7202  NC/ESD9B5V  [E0402]
ED7203  ESD9B5V  [E0402]
ED7204  ESD9B5V  [E0402]
ED7205  ESD9B5V  [E0402]
ED7206  NC/ESD9B5V  [E0402]
ED7207  NC/ESD9B5V  [E0402]
ED7208  NC/ESD9B5V  [E0402]
ED7209  NC/ESD9B5V  [E0402]
FB7200  0R  [R0603]
FB7201  BLM18EG601SN1  [L0603]
FB7202  BLM18EG601SN1  [L0603]
FB7203  BLM18EG601SN1  [L0603]
FB7204  BLM18EG601SN1  [L0603]
J7200  PJ-3536  [PJ-3536]
J7201  CON2  [SPKPAD]
J7202  CON2  [SPKPAD]
MIC7200  MIC  [MIC-4020]
R7200  0R/NC  [R0402]
R7201  NC/0R  [R0402]
R7202  33R  [R0402]
R7203  33R  [R0402]
R7204  33R  [R0402]
R7205  33R  [R0402]
R7206  33R  [R0402]
R7207  33R  [R0402]
R7208  10K  [R0402]
R7209  NC/10K  [R0402]
R7210  33R  [R0402]
R7211  0R  [R0402]
R7212  33R  [R0402]
R7213  33R  [R0402]
R7214  33R  [R0402]
R7215  4K7  [R0402]
R7216  4K7  [R0402]
R7217  2K2  [R0402]
R7218  100R  [R0402]
R7219  2K2  [R0402]
R7220  10K  [R0402]
R7221  33R  [L0603]
R7222  10K  [R0402]
R7223  33R  [L0603]
R7224  1K  [R0402]
R7225  2K2  [R0402]
R7226  22R  [R0402]
R7227  22R  [R0402]
R7228  100K  [R0402]
U7200  ALC3224  [763_ALC3224]
U7201  PT5108E23E-18  [SOT25]
sheet 75.TP COF
C7500  4.7uF  [C0603]
C7501  0.1uF  [C0402]
J7500  Touch_screen  [FPC12P_05MM]
R7500  4K7  [R0402]
R7501  4K7  [R0402]
T7500  TEST  [T-0.7]
T7501  TEST  [T-0.7]
T7502  TEST  [T-0.7]
T7503  TEST  [T-0.7]
T7504  TEST  [T-0.7]
T7505  TEST  [T-0.7]
sheet 76.TP COB-CT363 (option)
C7600  0.1uF  [C0402]
C7601  1uF/25V  [C0603]
C7602  1uF/50V  [C0805]
C7603  1uF/50V  [C0805]
C7604  4.7uF  [C0603]
C7605  0.1uF  [C0402]
C7606  1uF/25V  [C0603]
C7607  1uF/25V  [C0603]
C7608  1uF/50V  [C0805]
C7609  4.7uF  [C0603]
J7600  D97-L3312A  [D97-L3312A]
R7600  4K7  [R0402]
R7601  4K7  [R0402]
T7600  TEST  [T-0.7]
T7601  TEST  [T-0.7]
T7602  TEST  [T-0.7]
T7603  TEST  [T-0.7]
T7604  TEST  [T-0.7]
T7605  TEST  [T-0.7]
T7606  TEST  [T-0.7]
T7607  TEST  [T-0.7]
T7608  TEST  [T-0.7]
T7609  TEST  [T-0.7]
T7610  TEST  [T-0.7]
T7611  TEST  [T-0.7]
T7612  TEST  [T-0.7]
T7613  TEST  [T-0.7]
T7614  TEST  [T-0.7]
T7615  TEST  [T-0.7]
T7616  TEST  [T-0.7]
T7617  TEST  [T-0.7]
T7618  TEST  [T-0.7]
T7619  TEST  [T-0.7]
T7620  TEST  [T-0.7]
T7621  TEST  [T-0.7]
T7622  TEST  [T-0.7]
T7623  TEST  [T-0.7]
T7624  TEST  [T-0.7]
T7625  TEST  [T-0.7]
T7626  TEST  [T-0.7]
T7627  TEST  [T-0.7]
T7628  TEST  [T-0.7]
T7629  TEST  [T-0.7]
T7630  TEST  [T-0.7]
T7631  TEST  [T-0.7]
T7632  TEST  [T-0.7]
T7633  TEST  [T-0.7]
T7634  TEST  [T-0.7]
T7635  TEST  [T-0.7]
T7636  TEST  [T-0.7]
T7637  TEST  [T-0.7]
T7638  TEST  [T-0.7]
T7639  TEST  [T-0.7]
T7640  TEST  [T-0.7]
T7641  TEST  [T-0.7]
T7642  TEST  [T-0.7]
T7643  TEST  [T-0.7]
T7644  TEST  [T-0.7]
T7645  TEST  [T-0.7]
T7646  TEST  [T-0.7]
T7647  TEST  [T-0.7]
T7648  TEST  [T-0.7]
T7649  TEST  [T-0.7]
T7650  TEST  [T-0.7]
T7651  TEST  [T-0.7]
T7652  TEST  [T-0.7]
T7653  TEST  [T-0.7]
T7654  TEST  [T-0.7]
T7655  TEST  [T-0.7]
U7600  CT363  [QFN-68X0.4]
sheet 77.TP COB-FT5506 (option)
C7700  0.1uF  [C0402]
C7701  1uF  [C0402]
C7702  0.1uF  [C0402]
C7703  4.7uF  [C0603]
C7704  0.1uF  [C0402]
C7705  0.1uF  [C0402]
J7700  D97-L3312A  [D97-L3312A]
R7700  4K7  [R0402]
R7701  4K7  [R0402]
T7700  TEST  [T-0.7]
T7701  TEST  [T-0.7]
T7702  TEST  [T-0.7]
T7703  TEST  [T-0.7]
T7704  TEST  [T-0.7]
T7705  TEST  [T-0.7]
T7706  TEST  [T-0.7]
T7707  TEST  [T-0.7]
T7708  TEST  [T-0.7]
T7709  TEST  [T-0.7]
T7710  TEST  [T-0.7]
T7711  TEST  [T-0.7]
T7712  TEST  [T-0.7]
T7713  TEST  [T-0.7]
T7714  TEST  [T-0.7]
T7715  TEST  [T-0.7]
T7716  TEST  [T-0.7]
T7717  TEST  [T-0.7]
T7718  TEST  [T-0.7]
T7719  TEST  [T-0.7]
T7720  TEST  [T-0.7]
T7721  TEST  [T-0.7]
T7722  TEST  [T-0.7]
T7723  TEST  [T-0.7]
T7724  TEST  [T-0.7]
T7725  TEST  [T-0.7]
T7726  TEST  [T-0.7]
T7727  TEST  [T-0.7]
T7728  TEST  [T-0.7]
T7729  TEST  [T-0.7]
T7730  TEST  [T-0.7]
T7731  TEST  [T-0.7]
T7732  TEST  [T-0.7]
T7733  TEST  [T-0.7]
T7734  TEST  [T-0.7]
T7735  TEST  [T-0.7]
T7736  TEST  [T-0.7]
T7737  TEST  [T-0.7]
T7738  TEST  [T-0.7]
T7739  TEST  [T-0.7]
T7740  TEST  [T-0.7]
T7741  TEST  [T-0.7]
T7742  TEST  [T-0.7]
T7743  TEST  [T-0.7]
T7744  TEST  [T-0.7]
T7745  TEST  [T-0.7]
T7746  TEST  [T-0.7]
T7747  TEST  [T-0.7]
T7748  TEST  [T-0.7]
T7749  TEST  [T-0.7]
T7750  TEST  [T-0.7]
T7751  TEST  [T-0.7]
T7752  TEST  [T-0.7]
T7753  TEST  [T-0.7]
T7754  TEST  [T-0.7]
T7755  TEST  [T-0.7]
U7700  FT5506  [QFN68-8x8]
sheet 78.TP COB-GSL3680 (option)
C7800  10uF  [C0603]
C7801  0.1uF  [C0402]
C7802  0.1uF  [C0402]
J7800  CON50  [FPC50PIN_0.MM_DN]
R7800  4K7  [R0402]
R7801  4K7  [R0402]
T7800  TEST  [T-0.7]
T7801  TEST  [T-0.7]
T7802  TEST  [T-0.7]
T7803  TEST  [T-0.7]
T7804  TEST  [T-0.7]
T7805  TEST  [T-0.7]
T7806  TEST  [T-0.7]
T7807  TEST  [T-0.7]
T7808  TEST  [T-0.7]
T7809  TEST  [T-0.7]
T7810  TEST  [T-0.7]
T7811  TEST  [T-0.7]
T7812  TEST  [T-0.7]
T7813  TEST  [T-0.7]
T7814  TEST  [T-0.7]
T7815  TEST  [T-0.7]
T7816  TEST  [T-0.7]
T7817  TEST  [T-0.7]
T7818  TEST  [T-0.7]
T7819  TEST  [T-0.7]
T7820  TEST  [T-0.7]
T7821  TEST  [T-0.7]
T7822  TEST  [T-0.7]
T7823  TEST  [T-0.7]
T7824  TEST  [T-0.7]
T7825  TEST  [T-0.7]
T7826  TEST  [T-0.7]
T7827  TEST  [T-0.7]
T7828  TEST  [T-0.7]
T7829  TEST  [T-0.7]
T7830  TEST  [T-0.7]
T7831  TEST  [T-0.7]
T7832  TEST  [T-0.7]
T7833  TEST  [T-0.7]
T7834  TEST  [T-0.7]
T7835  TEST  [T-0.7]
T7836  TEST  [T-0.7]
T7837  TEST  [T-0.7]
T7838  TEST  [T-0.7]
T7839  TEST  [T-0.7]
T7840  TEST  [T-0.7]
T7841  TEST  [T-0.7]
T7842  TEST  [T-0.7]
T7843  TEST  [T-0.7]
T7844  TEST  [T-0.7]
T7845  TEST  [T-0.7]
T7846  TEST  [T-0.7]
T7847  TEST  [T-0.7]
U7800  GSL3680B  [QFN64-8X8-P0.4]
sheet 80.Sensor/VIB
C8000  1uF  [C0402]
C8001  4.7uF  [C0603]
C8002  0.1uF  [C0402]
C8003  0.22uF  [C0402]
C8004  0.1uF  [C0402]
C8005  0.1uF  [C0402]
C8006  0.1uF  [C0402]
C8007  0.1uF  [C0402]
C8008  0.1uF  [C0402]
C8009  10uF/10V  [C0805]
C8010  10nF  [C0402]
C8011  1uF  [C0402]
C8012  0.1uF  [C0402]
C8013  0.1uF  [C0402]
C8014  10nF  [C0402]
C8015  1uF  [C0402]
C8016  0.1uF  [C0402]
C8017  0.1uF  [C0402]
C8018  2.2nF  [C0402]
D8000  1N5819  [SOD123]
M8000  MOTO  [R1206]
Q8000  WNM2016  [SOT23]
R8000  300K  [R0402]
R8001  NC/0R  [R0402]
R8002  NC/0R  [R0402]
R8003  0R/NC  [R0402]
R8004  0R/NC  [R0402]
R8005  1K5  [R0402]
R8006  1K5  [R0402]
R8007  33R  [R0402]
R8008  NC  [R0402]
R8009  0R  [R0402]
R8010  1K  [R0402]
R8011  100K  [R0402]
R8012  100K  [R0402]
R8013  100K  [R0402]
U8000  CM3218/CM32131  [OPLGA6]
U8001  AK8963C  [BAG14-1.6X1.6]
U8002  LIS3DH/MMA8452Q/LSM303D  [LGA16]
U8003  OCH165TWAD  [SOT23]
U8004  LSM330TR  [LGA-24L]
U8005  MPU6050C  [MPU6050C]
sheet 81.TF Card
C8100  10uF  [C0603]
C8101  0.1uF  [C0402]
ED8100  AZ5725-01F  [E0402]
ED8101  AZ5725-01F  [E0402]
ED8102  AZ5725-01F  [E0402]
ED8103  AZ5725-01F  [E0402]
ED8104  AZ5725-01F  [E0402]
ED8105  AZ5725-01F  [E0402]
ED8106  AZ5725-01F  [E0402]
J8100  TF_SD_SOCKET  [TF-CKT01-009D]
R8100  33R  [R0402]
R8101  33R  [R0402]
R8102  33R  [R0402]
R8103  33R  [R0402]
R8104  33R  [R0402]
R8105  33R  [R0402]
R8106  33R  [R0402]
R8107  NC/10K  [R0402]
R8108  NC/10K  [R0402]
R8109  NC/10K  [R0402]
R8110  NC/10K  [R0402]
R8111  NC/10K  [R0402]
R8112  NC/10K  [R0402]
sheet 82.HDMI
C8200  0.1uF  [C0402]
J8200  HDMI_C  [HDMI-19PF_C]
Q8200  WNM2021/2SK3018  [SOT23]
Q8201  WNM2021/2SK3018  [SOT23]
R8200  NC  [R0402]
R8201  NC  [R0402]
R8202  1K  [R0402]
R8203  1K5  [R0402]
R8204  1K5  [R0402]
R8205  1K5  [R0402]
R8206  1K5  [R0402]
U8200  TPD4E05U06/AZ1045-04F  [SLP2510P8]
U8201  TPD4E05U06/AZ1045-04F  [SLP2510P8]
U8202  TPD4E05U06/AZ1045-04F  [SLP2510P8]
sheet 84.eFUSE (option)
C8400  NC/1uF  [C0402]
C8401  NC/0.1uF  [C0402]
C8402  NC/1uF  [C0402]
Q8400  NC/8050  [SOT23]
R8400  NC/100K  [R0402]
R8401  NC/10K  [R0402]
U8400  NC/PT5108E23E-15  [SOT25]

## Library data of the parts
U1000 = MCU_RK3288
C1400-C1402 C1500 = CAP_NP: 贴片电容; MARK: 106; ROOM: USB+5V
R1400 R1401 R1500-R1502 R8100-R8106 = RESISTOR_1
C1501 C6005 C6009 C6011 C7501 C7600 C7605 C7700-C7702 C7704 C7705 C7801 C7802 C8008 C8010 C8012-C8014 C8101 = CAP_NP: CAP,MLCC,100nF,+/-10%,X7R,6.3V,SMD0402
ED1500 ED7201 ED7202 ED8100-ED8106 = DIODE_BI-DIR_TRIG: ESD
SW1500 SW1501 = SW4P_0: 按键
T1500-T1502 T7500-T7505 T7600-T7655 T7700-T7755 T7800-T7847 = TESTPOINT1
C6000 C6002 = CAP_NP: RoHS CHIP CAP 10pF +10/-10% X7R
C6001 C6012 C8001 = CAP_NP: RoHS CHIP CAP 4.7uF +10/-10% X5R
C6003 C6004 C7219 C7224 C7225 C7227 C7500 C7601-C7604 C7606-C7609 C7703 C7800 C8002 C8007 C8200 C8400-C8402 = CAP_NP
C6006 C6007 = CAP_NP: RoHS CHIP CAP 8pF +/-1% NPO
C6008 C6010 C8011 C8100 = CAP_NP: CAP,MLCC,10uF,+/-10%,X5R,6.3V,SMD0805
C6013 = CAP_NP: RoHS CHIP CAP 2.2uF +10/-10% X5R
J6000 = ANT3: ANT
L6000 = INDUCTORS_OF_FERRITE
R6000-R6005 = RESISTOR: RES,thick film,33Ohm,+/-5%,1/16W,SMD0402
R6006 = RES_1B: ROHS CHIP RES 560K 1/16W +/-5%
R6007 = RES_1B: ROHS CHIP RES 100 Ohm 1/16W +/-5%
R6008 R7215-R7217 R7500 R7501 R7600 R7601 R7700 R7701 R7800 R7801 R8005 R8006 R8008 R8011-R8013 R8400 R8401 = RESISTOR_0
R6009-R6013 R8107-R8112 = RESISTOR: ROHS CHIP RES 10K 1/16W +/-5%
RP6000 = RESISTOR_4PACK: ROHS CHIP RES 10K 1/16W +/-5%
U6000 = WIFI-AP6XXX: WIFI&BT; ORCAD_LIB: MODULE; QVL: AMPAK
U6001 = LM1086_2
Y6000 = CRYSTAL-4: Crystal,24.000MHz,+/-20ppm,12pF,SMD3225,-10°C ~ +60   °C
C7200-C7202 C7213-C7217 C7220-C7223 C8004 C8005 C8016 = CAP_NP: RoHS CHIP CAP 0.1uF +10/-10% X7R
C7203 C7205-C7207 C7218 = CAP_v2: RoHS CHIP CAP 2.2uF +10/-10% X5R
C7204 C7226 C7233-C7235 = CAP_v2: RoHS CHIP CAP 0.1uF +10/-10% X7R
C7208-C7211 = CAP_v2: RoHS CHIP CAP 0.1uF +10/-10% 16V X5R
C7212 = CAP_v2: RoHS CHIP CAP 4.7uF +10/-10% X5R
C7228-C7230 = CAP_v2: RoHS CHIP CAP 0.01uF +10/-10% X7R
C7231 C7232 C7236 = CAP_NP: RoHS CHIP CAP 100pF +10/-10% X7R
C7237-C7240 = CAP_NP: CAP,MLCC,680pF,+/-10%,NPO,6.3V,SMD0402
ED7200 ED7203-ED7205 = TVS: ESD Component,5V,30P,SMD,0402
ED7206-ED7209 = DIODE_BI-DIR_TRIG: NC/ESD Component,5V,30P,SMD,0402
FB7200 = INDUCTOR: ROHS CHIP RES 0 Ohm 1/16W +/-5%
FB7201-FB7204 = INDUCTOR: FB,Multilayer,180Ohm@100MHz,+/-25%,1500mA,,SMD0603
J7200 = PJ-3536
J7201 J7202 = CON2_0: Speaker Connector, 2pin, SMT
MIC7200 = MIC
R7200 R7201 R7211 = RES_1B
R7202-R7207 R7210 R7212-R7214 = RESISTOR: ROHS CHIP RES 33R 1/16W 5%
R7208 R7209 = RESISTOR: ROHS CHIP RES 10K 1/16W 5%
R7218 = RESISTOR_1: RES,thick film,10KOhm,+/-5%,1/16W,SMD0402
R7219 = RESISTOR: ROHS CHIP RES 2K2 1/16W 5%
R7220 R7222 = RESISTOR: ROHS CHIP RES 0R 1/16W 5%
R7221 R7223 = INDUCTOR: ROHS CHIP RES 33R 1/16W 5%
R7224 R7228 = RESISTOR: ROHS CHIP RES 1K 1/16W 5%
R7225 = RESISTOR_0: 贴片电阻
R7226 R7227 = RESISTOR: ROHS CHIP RES 22R 1/16W 5%
U7200 = CODEC-ALC3224: CODEC
U7201 U8400 = LDO-PT5108_RT9013
J7500 = touch_screen_0
J7600 J7700 = TP-54P
U7600 = Touch-CT363
U7700 = FT5506
J7800 = CLAP070LF02CW_8: NC
U7800 = GSL3680_1
C8000 = CAP_NP: CAP,MLCC,680nF,+/-10%,X7R,6.3V,SMD0402
C8003 = CAP_NP: RoHS CHIP CAP 0.22uF +10/-10% X7R
C8006 = CAP_NP: CAP,MLCC,8pF,+/-10%,NPO,6.3V,SMD0402
C8009 = CAP_NP: CAP,MLCC,10uF,+/-10%,X5R,6.3V,SMD0805; MARK: 105
C8015 C8017 C8018 = CAP_NP: CAP,MLCC,1uF,+/-10%,X5R,6.3V,SMD0402; ROOM: CHG
D8000 = DIODE: Diode,Schottky,1N5819HW,40V,1A,SOD-123
M8000 = MOTOR_SERVO: Vibration,R1206,SMT
Q8000 Q8200 Q8201 = FET_N_MOS
R8000 = RESISTOR_0: 贴片电阻; MARK: 51K
R8001 = RESISTOR: ROHS CHIP RES 0 Ohm 1/16W +/-5%
R8002-R8004 = RESISTOR: NC/ROHS CHIP RES 0R 1/16W +/-5%
R8007 = RESISTOR_0: RES,thick film,43Ohm,+/-1%,1/8W,SMD0805
R8009 = RESISTOR_0: RES,thick film,0Ohm,+/-5%,1/16W,SMD0402
R8010 = RESISTOR_0: RES,thick film,47KOhm,+/-5%,1/16W,SMD0402
U8000 = CM3217_1
U8001 = Sensor-AK8963C
U8002 = MMA8452Q: G_Sensor,LIS3DH/MMA8452Q,1.95V~3.6V,LGA-16,3X3X1.0,-40°C ~ +85°C
U8003 = Hallsensor
U8004 = LSM330
U8005 = MPU6050C_0
J8100 = SD_SOCKET_0
J8200 = HDMI_C: HDMI Connector,19pin,SMT
R8200-R8202 = RES_1B: ROHS CHIP RES 4.7KOhm, 1/16W +/-5%
R8203-R8206 = RESISTOR
U8200-U8202 = DS8008_2: NC
Q8400 = NPN4

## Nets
AVDD18_CODEC: C7219.2 C7220.1 C7221.1 R7211.1 U7200.15(AVDD) U7200.23(CPVDD) U7201.5(OUT)
AVDD18_REF: C7222.1 C7223.1 R7211.2 U7200.10(DACRFE)
GND: C1400.1 C1401.1 C1402.1 C1500.1 C1501.1 C6001.1 C6002.1 C6003.2 C6004.2 C6005.2 C6006.1 C6007.1 C6008.1 C6009.2 C6010.1 C6011.2 C6012.1 C6013.1 C7200.2 C7201.2 C7202.2 C7204.1 C7206.1 C7207.1 C7211.2 C7212.2 C7213.2 C7214.2 C7215.2 C7216.2 C7217.2 C7218.2 C7219.1 C7220.2 C7221.2 C7222.2 C7223.2 C7224.2 C7225.2 C7226.2 C7227.1 C7228.2 C7229.2 C7230.2 C7232.1 C7235.2 C7236.1 C7237.1 C7238.1 C7239.2 C7240.2 C7500.2 C7501.2 C7600.2 C7604.2 C7605.2 C7606.2 C7607.2 C7608.2 C7609.2 C7700.2 C7701.2 C7702.2 C7703.2 C7704.2 C7705.2 C7800.2 C7801.2 C7802.2 C8000.2 C8001.2 C8002.1 C8004.1 C8005.1 C8006.1 C8007.1 C8008.1 C8009.1 C8010.1 C8011.1 C8012.1 C8013.1 C8014.2 C8015.1 C8016.1 C8017.2 C8018.1 C8100.1 C8101.2 C8200.2 C8400.2 C8401.2 C8402.1 ED1500.2 ED7200.2 ED7201.2 ED7202.2 ED7203.2 ED7204.2 ED7205.2 ED7206.2 ED7207.2 ED7208.2 ED7209.2 ED8100.2 ED8101.2 ED8102.2 ED8103.2 ED8104.2 ED8105.2 ED8106.2 J6000.2(GND) J7200.1 J7500.1(GND) J7500.6(GND) J7500.13(GND) J7500.14(GND) J7600.1(GND) J7600.32(GND) J7600.33(GND) J7600.54(GND) J7600.55(GND) J7600.56(GND) J7700.1(GND) J7700.32(GND) J7700.33(GND) J7700.54(GND) J7700.55(GND) J7700.56(GND) J7800.4(GND) J7800.21(GND) J7800.22(GND) J7800.49(GND) J7800.50(GND) J7800.51(GND) J7800.52(GND) J8100.6(VSS) J8100.10(G1) J8100.11(G2) J8100.12(G3) J8100.13(G4) J8200.1 J8200.4 J8200.7 J8200.10 J8200.13 J8200.20 J8200.21 J8200.22 J8200.23 Q8000.2(SOURCE) Q8400.2(E) R1400.1 R1401.1 R7209.2 R7222.1 R7225.1 R7226.1 R7227.1 R8000.2 R8001.1 R8009.1 R8013.2 SW1500.1 SW1500.2 SW1501.1 SW1501.2 T1502.1 T7505.1 T7601.1 T7702.1 T7801.1 U1000.B21(USB_AVSS4) U1000.C24(USB_AVSS2) U1000.C26(USB_AVSS3) U1000.H18(USB_AVSS1) U6000.1(GND) U6000.3(GND) U6000.20(GND) U6000.31(GND) U6000.33(GND) U6000.36(GND) U6001.2(GND) U7200.9(AGND) U7200.22(CPGND) U7200.25(HPOFB) U7200.49(PADGND) U7201.2(GND) U7600.6(GND) U7600.69(GND) U7700.10(VSS1) U7700.39(VSS2) U7700.41(VSSD) U7700.45(MOSI) U7700.50(VSSA) U7700.61(VSS3) U7700.69(VSS4) U7800.19(DVSS) U7800.46(GND) U7800.65(GND) U7800.66(GND) U7800.67(GND) U7800.68(GND) U8000.1(GND) U8001.C1(VSS) U8001.D2(CAD1) U8002.5(GND) U8002.10(GND) U8002.12(GND) U8002.13(NC) U8002.16(NC) U8003.3(GND) U8004.5(SDO_G) U8004.6(SDO_A) U8004.14(RES1) U8004.15(RES2) U8004.16(RES3) U8004.17(RES4) U8004.18(RES5) U8004.19(GND) U8004.20(GND) U8005.1(CLKIN) U8005.11(FSYNC) U8005.18(GND) U8200.3(GND) U8200.8(GND) U8201.3(GND) U8201.8(GND) U8202.3(GND) U8202.8(GND) U8400.2(GND) Y6000.2(GND) Y6000.4(GND) ; also on sheet 5 6 7 8 9 10 11 12 13 14 15 16 17 18 19 20 21 22 23 24 25 26 27 28 29 30 31 32 33 34 47 48
VCC50_BOOST: C8200.1 J8200.18 R8204.1 R8206.1 ; also on sheet 13 14
VCC_18: C1401.2 C1500.2 R1500.2 R7201.1 U1000.E21(USB_AVDD_1V8) U1000.R20(ADC_AVDD_1V8) ; also on sheet 13 14 17 18 19 20 32 33 34
VCC_EFUSE: C8402.2 U8400.5(OUT) ; also on sheet 6
VCC_IO: C8002.2 C8004.2 C8005.2 C8007.2 C8011.2 C8012.2 C8013.2 C8014.1 C8015.2 C8016.2 C8400.1 Q8200.1(GATE) Q8201.1(GATE) R7200.1 R8002.2 R8005.1 R8006.1 R8008.2 R8011.1 R8012.1 R8203.1 R8205.1 R8400.2 U8001.A2(CSB) U8001.B1(VDD) U8001.C4(VID) U8001.D1(CAD0) U8001.D4(RST) U8002.1(VDDIO) U8002.7(SA0) U8002.8(NC) U8002.14(VDD) U8004.1(VDD_IO) U8004.3(VDD_IO) U8004.7(CS_G) U8004.8(CS_A) U8004.22(VDD) U8004.23(VDD) U8004.24(VDD) U8005.8(VLOGIC) U8005.13(VDD) U8400.1(IN) ; also on sheet 11 13 14 21 22 23 24 31 32 33 34
VCC_SD: C8100.2 C8101.1 J8100.4(VDD) ; also on sheet 13 14
VCC_SPK: C7214.1 C7215.1 FB7200.2 U7200.2(SPKVDDL) U7200.46(SPKVDDR) ; also on sheet 34
VCC_SYS: C7213.1 C8008.2 C8009.2 FB7200.1 R8007.1 ; also on sheet 13 14 24 27 28 29 30 33 34
VCC_TP: C7500.1 C7501.1 C7604.1 C7605.1 C7703.1 C7704.1 C7705.1 C7800.1 C7801.1 C7802.1 C8000.1 J7500.11(VDD) J7500.12(VDD) R7500.1 R7501.1 R7600.1 R7601.1 R7700.1 R7701.1 R7800.1 R7801.1 T7504.1 T7650.1 T7755.1 T7847.1 U7600.7(VDDIO) U7600.8(VDD) U7700.38(VDD3) U7700.48(IOVCC) U7700.49(VDDA) U7800.3(AVDD) U7800.26(VDDIO) U8000.6(VDD) ; also on sheet 13 14
VCC_WL: C6004.1 C6005.1 C6008.2 C6009.1 C6013.2 R6008.1 R6009.1 R6010.1 R6011.1 R6012.1 R6013.1 RP6000.1 RP6000.2 RP6000.3 RP6000.4 U6000.22(VDDIO) U6000.29(VDD_TCXO) U6001.5(Vcc) ; also on sheet 11 13 14 47 48
VCC_WLIN: C6001.2 C6010.2 C6011.1 U6000.9(VBAT) ; also on sheet 13 14 47 48
VCCA_CODEC: C7200.1 C7201.1 C7202.1 C7224.1 C7226.1 R7219.2 U7200.3(MICVDD) U7201.1(IN) U7201.3(EN) ; also on sheet 13 14 31 32 33 34
VCCIO_CODEC: C7204.2 R7200.2 R7201.2 R7208.2 R7215.1 R7216.1 U7200.43(DBVDD) ; also on sheet 11 32 33 34
VCCIO_PMU: C1402.2 C8006.2 R7228.1 R8200.1 U1000.F20(USB_AVDD_3V3) U8003.1(VDD) ; also on sheet 6 11 13 14 17 18 19 20 24 33 34
VCCIO_SD: R8107.1 R8108.1 R8109.1 R8110.1 R8111.1 R8112.1 ; also on sheet 11 13 14
VDD_10: C1400.2 U1000.G18(USB_AVDD_1V0) U1000.H20(HSIC_AVDD_1V2) ; also on sheet 6 13 14
VDD_CODEC: C7216.1 C7217.1 U7200.42(DCVDD)
3G_IN_L: U7200.16(LOUTL) ; also on sheet 31 32
3G_IN_R: U7200.17(LOUTR) ; also on sheet 31 32
3G_OUT_N: U7200.14(MONON) ; also on sheet 31 32
3G_OUT_P: U7200.13(MONOP) ; also on sheet 31 32
AD0: R8008.1 R8009.2 U8005.9(AD0)
ADCIN2: C7228.1 C7229.1 C7230.1 R7220.1 R7222.2 U1000.P23(ADC_IN2)
ADKEY_IN: C1501.2 ED1500.1 R1500.1 R1501.1 R1502.1 U1000.P21(RECOVER/ADC_IN1)
BT_HOST_WAKE: R6013.2 U6000.7(BT_HOST_WAKE) ; also on sheet 11 47 48
BT_PCM_CLK: R7210.2 U6000.26(PCM_CLK) ; also on sheet 47 48
BT_PCM_IN: R7213.2 U6000.25(PCM_OUT) ; also on sheet 47 48
BT_PCM_OUT: R7214.2 U6000.27(PCM_IN) ; also on sheet 47 48
BT_PCM_SYNC: R7212.2 U6000.28(PCM_SYNC) ; also on sheet 47 48
BT_RST: U6000.34(BT_RST_N) ; also on sheet 11 47 48
BT_WAKE: U6000.6(BT_WAKE) ; also on sheet 11 47 48
CODEC_IN1N: C7209.2 C7231.1 C7236.2 ED7202.1 MIC7200.2 R7225.2
CODEC_IN1P: C7208.2 C7231.2 C7232.2 ED7201.1 MIC7200.1 R7217.1
COMP_INT: R8004.2 U8001.A1(DRDY) ; also on sheet 11
DDC_SCL: J8200.15 Q8200.3(DRAIN) R8204.2 U8202.2(IN2) U8202.9(OUT2)
DDC_SDA: J8200.16 Q8201.3(DRAIN) R8206.2 U8202.4(IN3) U8202.7(OUT3)
DRIVER1: J7600.31(D30) T7634.1 U7600.47(AIN29)
DRIVER2: J7600.30(D29) T7633.1 U7600.46(AIN28)
DRIVER3: J7600.29(D28) T7632.1 U7600.45(AIN27)
DRIVER4: J7600.28(D27) T7631.1 U7600.44(AIN26)
DRIVER5: J7600.27(D26) T7630.1 U7600.43(AIN25)
DRIVER6: J7600.26(D25) T7629.1 U7600.42(AIN24)
DRIVER7: J7600.25(D24) T7628.1 U7600.41(AIN23)
DRIVER8: J7600.24(D23) T7627.1 U7600.40(AIN22)
DRIVER9: J7600.23(D22) T7626.1 U7600.39(AIN21)
DRIVER10: J7600.22(D21) T7625.1 U7600.38(AIN20)
DRIVER11: J7600.21(D20) T7624.1 U7600.37(AIN19)
DRIVER12: J7600.20(D19) T7623.1 U7600.36(AIN18)
DRIVER13: J7600.19(D18) T7622.1 U7600.35(AIN17)
DRIVER14: J7600.18(D17) T7621.1 U7600.34(AIN16)
DRIVER15: J7600.17(D16) T7620.1 U7600.33(AIN15)
DRIVER16: J7600.16(D15) T7619.1 U7600.32(AIN14)
DRIVER17: J7600.15(D14) T7605.1 U7600.31(AIN13)
DRIVER18: J7600.14(D13) T7618.1 U7600.30(AIN12)
DRIVER19: J7600.13(D12) T7617.1 U7600.29(AIN11)
DRIVER20: J7600.12(D11) T7604.1 U7600.28(AIN10)
DRIVER21: J7600.11(D10) T7616.1 U7600.27(AIN9)
DRIVER22: J7600.10(D09) T7615.1 U7600.26(AIN8)
DRIVER23: J7600.9(D08) T7614.1 U7600.25(AIN7)
DRIVER24: J7600.8(D07) T7613.1 U7600.24(AIN6)
DRIVER25: J7600.7(D06) T7612.1 U7600.23(AIN5)
DRIVER26: J7600.6(D05) T7611.1 U7600.22(AIN4)
DRIVER27: J7600.5(D04) T7610.1 U7600.21(AIN3)
DRIVER28: J7600.4(D03) T7609.1 U7600.20(AIN2)
DRIVER29: J7600.3(D02) T7608.1 U7600.19(AIN1)
DRIVER30: J7600.2(D01) T7606.1 U7600.18(AIN0)
DRIVER-1: J7700.31(D30) T7734.1 U7700.63(TX1)
DRIVER-2: J7700.30(D29) T7733.1 U7700.64(TX2)
DRIVER-3: J7700.29(D28) T7732.1 U7700.65(TX3)
DRIVER-4: J7700.28(D27) T7731.1 U7700.66(TX4)
DRIVER-5: J7700.27(D26) T7730.1 U7700.67(TX5)
DRIVER-6: J7700.26(D25) T7729.1 U7700.68(TX6)
DRIVER-7: J7700.25(D24) T7728.1 U7700.1(TX7)
DRIVER-8: J7700.24(D23) T7727.1 U7700.2(TX8)
DRIVER-9: J7700.23(D22) T7726.1 U7700.3(TX9)
DRIVER-10: J7700.22(D21) T7725.1 U7700.4(TX10)
DRIVER-11: J7700.21(D20) T7724.1 U7700.5(TX11)
DRIVER-12: J7700.20(D19) T7723.1 U7700.6(TX12)
DRIVER-13: J7700.19(D18) T7722.1 U7700.7(TX13)
DRIVER-14: J7700.18(D17) T7721.1 U7700.8(TX14)
DRIVER-15: J7700.17(D16) T7720.1 U7700.9(TX15)
DRIVER-16: J7700.16(D15) T7719.1 U7700.11(TX16)
DRIVER-17: J7700.15(D14) T7712.1 U7700.12(TX17)
DRIVER-18: J7700.14(D13) T7711.1 U7700.13(TX18)
DRIVER-19: J7700.13(D12) T7710.1 U7700.14(TX19)
DRIVER-20: J7700.12(D11) T7709.1 U7700.15(TX20)
DRIVER-21: J7700.11(D10) T7718.1 U7700.16(TX21)
DRIVER-22: J7700.10(D09) T7717.1 U7700.17(TX22)
DRIVER-23: J7700.9(D08) T7716.1 U7700.18(TX23)
DRIVER-24: J7700.8(D07) T7715.1 U7700.19(TX24)
DRIVER-25: J7700.7(D06) T7714.1 U7700.20(TX25)
DRIVER-26: J7700.6(D05) T7708.1 U7700.21(TX26)
DRIVER-27: J7700.5(D04) T7707.1 U7700.22(TX27)
DRIVER-28: J7700.4(D03) T7706.1 U7700.23(TX28)
DRIVER-29: J7700.3(D02) T7705.1 U7700.24(TX29)
DRIVER-30: J7700.2(D01) T7704.1 U7700.25(TX30)
DRV0: J7800.23(TX1) T7821.1 U7800.41(X11)
DRV1: J7800.24(TX2) T7822.1 U7800.40(X10)
DRV2: J7800.25(TX3) T7823.1 U7800.39(X9)
DRV3: J7800.26(TX4) T7824.1 U7800.38(X8)
DRV4: J7800.27(TX5) T7825.1 U7800.37(X7)
DRV5: J7800.28(TX6) T7826.1 U7800.36(X6)
DRV6: J7800.29(TX7) T7827.1 U7800.35(X5)
DRV7: J7800.30(TX8) T7828.1 U7800.34(X4)
DRV8: J7800.31(TX9) T7829.1 U7800.33(X3)
DRV9: J7800.32(TX10) T7830.1 U7800.32(X2)
DRV10: J7800.33(TX11) T7831.1 U7800.31(X1)
DRV11: J7800.34(TX12) T7832.1 U7800.30(X0)
DRV12: J7800.35(TX13) T7833.1 U7800.5(X29)
DRV13: J7800.36(TX14) T7834.1 U7800.6(X28)
DRV14: J7800.37(TX15) T7835.1 U7800.7(X27)
DRV15: J7800.38(TX16) T7836.1 U7800.8(X26)
DRV16: J7800.39(TX17) T7837.1 U7800.9(X25)
DRV17: J7800.40(TX18) T7838.1 U7800.10(X24)
DRV18: J7800.41(TX19) T7839.1 U7800.11(X23)
DRV19: J7800.42(TX20) T7840.1 U7800.12(X22)
DRV20: J7800.43(TX21) T7841.1 U7800.13(X21)
DRV21: J7800.44(TX22) T7842.1 U7800.14(X20)
DRV22: J7800.45(TX23) T7843.1 U7800.15(X19)
DRV23: J7800.46(TX24) T7844.1 U7800.16(X18)
DRV24: J7800.47(TX25) T7845.1 U7800.17(X17)
DRV25: J7800.48(TX26) T7846.1 U7800.18(X16)
EFUSE_PWR: R8401.1 ; also on sheet 6
GSEN_INT: U8002.11(INT1) U8004.11(INT1_A) U8005.12(INT) ; also on sheet 11
GYR_INT: R8011.2 U8004.10(INT_G) ; also on sheet 11
HALL_INT: U8003.2(OUT) ; also on sheet 6
HDMI_CEC: R8201.2 ; also on sheet 11
HDMI_HPD: R8202.2 ; also on sheet 10
HDMI_TX0N: J8200.9 U8201.2(IN2) U8201.9(OUT2) ; also on sheet 10
HDMI_TX0P: J8200.8 U8201.1(IN1) U8201.10(OUT1) ; also on sheet 10
HDMI_TX1N: J8200.6 U8200.5(IN4) U8200.6(OUT4) ; also on sheet 10
HDMI_TX1P: J8200.5 U8200.4(IN3) U8200.7(OUT3) ; also on sheet 10
HDMI_TX2N: J8200.3 U8200.2(IN2) U8200.9(OUT2) ; also on sheet 10
HDMI_TX2P: J8200.2 U8200.1(IN1) U8200.10(OUT1) ; also on sheet 10
HDMI_TXCN: J8200.12 U8201.5(IN4) U8201.6(OUT4) ; also on sheet 10
HDMI_TXCP: J8200.11 U8201.4(IN3) U8201.7(OUT3) ; also on sheet 10
HOST2_DM: U1000.A22(HOST2_DM) ; also on sheet 31 32
HOST2_DP: U1000.B22(HOST2_DP) ; also on sheet 31 32
HP_DET: C7235.1 R7224.2 R7228.2 ; also on sheet 11 33 34
HP_HOOK: C7210.2 ED7205.1 J7200.2 R7219.1 R7220.2
HPOUTL: C7234.1 R7223.2 U7200.28(HPO_L)
HPOUTR: C7233.1 R7221.2 U7200.26(HPO_R)
I2C1_SCL_Sensor: R8006.2 U8000.5(SCLK) U8001.A3(SCL/SK) U8002.4(SCL) U8004.2(SCL_A/G) U8005.23(SCL) ; also on sheet 11
I2C1_SDA_Sensor: R8005.2 U8000.2(SDAT) U8001.A4(SDA/SI) U8002.6(SDA) U8004.4(SDA/SDI_A/G) U8005.24(SDA) ; also on sheet 11
I2C2_SCL_AUDIO: R7215.2 U7200.38(SCL) ; also on sheet 11 31 32 33 34
I2C2_SDA_AUDIO: R7216.2 U7200.39(SDA) ; also on sheet 11 31 32 33 34
I2C4_SCL_TP: J7500.8(SCL) R7501.2 R7600.2 R7700.2 R7800.2 T7503.1 T7607.1 T7713.1 T7808.1 U7600.4(SCK) U7700.47(SCL/SSEL) U7800.22(SCL) ; also on sheet 11 30
I2C4_SDA_TP: J7500.7(SDA) R7500.2 R7601.2 R7701.2 R7801.2 T7502.1 T7603.1 T7703.1 T7807.1 U7600.3(SDA) U7700.46(SDA/SCK) U7800.21(SDA) ; also on sheet 11 30
I2C5_SCL_HDMI: Q8200.2(SOURCE) R8203.2 ; also on sheet 11
I2C5_SDA_HDMI: Q8201.2(SOURCE) R8205.2 ; also on sheet 11
I2S0_CLK: R7202.1 ; also on sheet 11 31 32 33 34
I2S0_LRCK_RX: R7205.1 ; also on sheet 11 33 34
I2S0_LRCK_TX: R7204.1 ; also on sheet 11 33 34
I2S0_SCLK: R7203.1 ; also on sheet 11 33 34
I2S0_SDI: R7207.1 ; also on sheet 11 33 34
I2S0_SDO0: R7206.1 ; also on sheet 11 33 34
LDO1_EN: R7208.1 R7209.1 U7200.44(LDO1_EN)
LIGHT_INT: R8012.2 U8000.3(INT) ; also on sheet 11
MCLK_IN: U6000.30(TCXO_IN) U6001.6(OUT_Y1)
MICBIAS1: R7218.1 U7200.4(MICBAIS1) ; also on sheet 34
OTG_DET: U1000.D23(OTG_VBUS) ; also on sheet 12
OTG_DM: U1000.A26(OTG_DM) ; also on sheet 12
OTG_DP: U1000.B26(OTG_DP) ; also on sheet 12
OTG_ID: U1000.C25(OTG_ID) ; also on sheet 12
PORT_CEC: J8200.14 R8200.2 R8201.1 U8202.1(IN1) U8202.10(OUT1)
PORT_HPD: J8200.19 R8202.1 U8202.5(IN4) U8202.6(OUT4)
RTC_CLKOUT2: R6008.2 U6000.24(LPO) ; also on sheet 13 14 47 48
SDIO_CLK: R6005.1 U6000.17(SDIO_DATA_CLK)
SDIO_CMD: R6004.1 U6000.16(SDIO_DATA_CMD)
SDIO_D0: R6000.1 U6000.18(SDIO_DATA_0)
SDIO_D1: R6001.1 U6000.19(SDIO_DATA_1)
SDIO_D2: R6002.1 U6000.14(SDIO_DATA_2)
SDIO_D3: R6003.1 U6000.15(SDIO_DATA_3)
SDMMC_CLK: R8103.1 ; also on sheet 11
SDMMC_CMD: R8102.1 R8111.2 ; also on sheet 11
SDMMC_D0: R8104.1 R8107.2 ; also on sheet 11
SDMMC_D1: R8105.1 R8108.2 ; also on sheet 11
SDMMC_D2: R8100.1 R8109.2 ; also on sheet 11
SDMMC_D3: R8101.1 R8110.2 ; also on sheet 11
SDMMC_DET: R8106.1 R8112.2 ; also on sheet 11
SENS0: J7800.20(RX1) T7820.1 U7800.62(Y15)
SENS1: J7800.19(RX2) T7819.1 U7800.61(Y14)
SENS2: J7800.18(RX3) T7818.1 U7800.60(Y13)
SENS3: J7800.17(RX4) T7817.1 U7800.59(Y12)
SENS4: J7800.16(RX5) T7816.1 U7800.58(Y11)
SENS5: J7800.15(RX6) T7815.1 U7800.57(Y10)
SENS6: J7800.14(RX7) T7814.1 U7800.56(Y9)
SENS7: J7800.13(RX8) T7813.1 U7800.55(Y8)
SENS8: J7800.12(RX9) T7805.1 U7800.54(Y7)
SENS9: J7800.11(RX10) T7804.1 U7800.53(Y6)
SENS10: J7800.10(RX11) T7803.1 U7800.52(Y5)
SENS11: J7800.9(RX12) T7802.1 U7800.51(Y4)
SENS12: J7800.8(RX13) T7812.1 U7800.50(Y3)
SENS13: J7800.7(RX14) T7811.1 U7800.49(Y2)
SENS14: J7800.6(RX15) T7810.1 U7800.48(Y1)
SENS15: J7800.5(RX16) T7809.1 U7800.47(Y0)
SENSOR0: J7600.53(S1) T7655.1 U7600.67(AIN49)
SENSOR1: J7600.52(S2) T7654.1 U7600.66(AIN48)
SENSOR2: J7600.51(S3) T7653.1 U7600.65(AIN47)
SENSOR3: J7600.50(S4) T7652.1 U7600.64(AIN46)
SENSOR4: J7600.49(S5) T7651.1 U7600.63(AIN45)
SENSOR5: J7600.48(S6) T7649.1 U7600.62(AIN44)
SENSOR6: J7600.47(S7) T7648.1 U7600.61(AIN43)
SENSOR7: J7600.46(S8) T7647.1 U7600.60(AIN42)
SENSOR8: J7600.45(S9) T7646.1 U7600.59(AIN41)
SENSOR9: J7600.44(S10) T7645.1 U7600.58(AIN40)
SENSOR10: J7600.43(S11) T7644.1 U7600.57(AIN39)
SENSOR11: J7600.42(S12) T7643.1 U7600.56(AIN38)
SENSOR12: J7600.41(S13) T7642.1 U7600.55(AIN37)
SENSOR13: J7600.40(S14) T7641.1 U7600.54(AIN36)
SENSOR14: J7600.39(S15) T7640.1 U7600.53(AIN35)
SENSOR15: J7600.38(S16) T7639.1 U7600.52(AIN34)
SENSOR16: J7600.37(S17) T7638.1 U7600.51(AIN33)
SENSOR17: J7600.36(S18) T7637.1 U7600.50(AIN32)
SENSOR18: J7600.35(S19) T7636.1 U7600.49(AIN31)
SENSOR19: J7600.34(S20) T7635.1 U7600.48(AIN30)
SENSOR-1: J7700.53(S1) T7754.1 U7700.51(RX1)
SENSOR-2: J7700.52(S2) T7753.1 U7700.52(RX2)
SENSOR-3: J7700.51(S3) T7752.1 U7700.53(RX3)
SENSOR-4: J7700.50(S4) T7751.1 U7700.54(RX4)
SENSOR-5: J7700.49(S5) T7750.1 U7700.55(RX5)
SENSOR-6: J7700.48(S6) T7749.1 U7700.56(RX6)
SENSOR-7: J7700.47(S7) T7748.1 U7700.57(RX7)
SENSOR-8: J7700.46(S8) T7747.1 U7700.58(RX8)
SENSOR-9: J7700.45(S9) T7746.1 U7700.59(RX9)
SENSOR-10: J7700.44(S10) T7745.1 U7700.60(RX10)
SENSOR-11: J7700.43(S11) T7744.1 U7700.37(RX11)
SENSOR-12: J7700.42(S12) T7743.1 U7700.36(RX12)
SENSOR-13: J7700.41(S13) T7742.1 U7700.35(RX13)
SENSOR-14: J7700.40(S14) T7741.1 U7700.34(RX14)
SENSOR-15: J7700.39(S15) T7740.1 U7700.33(RX15)
SENSOR-16: J7700.38(S16) T7739.1 U7700.32(RX16)
SENSOR-17: J7700.37(S17) T7738.1 U7700.31(RX17)
SENSOR-18: J7700.36(S18) T7737.1 U7700.30(RX18)
SENSOR-19: J7700.35(S19) T7736.1 U7700.29(RX19)
SENSOR-20: J7700.34(S20) T7735.1 U7700.28(RX20)
SPK_LN: FB7203.1 U7200.48(SPO_LN)
SPK_LP: FB7201.1 U7200.1(SPO_LP)
SPK_RN: FB7204.1 U7200.47(SPO_RN)
SPK_RP: FB7202.1 U7200.45(SPO_RP)
TOUCH_INT: J7500.10(INT) T7501.1 T7602.1 T7701.1 T7806.1 U7600.2(SS) U7700.43(GPIO6/~{WAKE}) U7800.27(IRQ) ; also on sheet 11
TOUCH_RST: C7600.1 C7700.1 J7500.9(/SD) T7500.1 T7600.1 T7700.1 T7800.1 U7600.68(RSTB) U7700.42(~{RST}) U7800.28(~{SHUTDOWN}) ; also on sheet 11
UART0_CTS: U6000.41(UART_RTS_N) ; also on sheet 11 47 48
UART0_RTS: R6011.2 U6000.44(UART_CTS_N) ; also on sheet 11 47 48
UART0_RXD: R6012.2 U6000.42(UART_TXD) ; also on sheet 11 47 48
UART0_TXD: U6000.43(UART_RXD) ; also on sheet 11 47 48
VIB_CTL: R8010.2 R8013.1 ; also on sheet 11
WIFI_CLK: R6005.2 ; also on sheet 11 47 48
WIFI_CMD: R6004.2 R6009.2 ; also on sheet 11 47 48
WIFI_D0: R6000.2 RP6000.7 ; also on sheet 11 47 48
WIFI_D1: R6001.2 RP6000.8 ; also on sheet 11 47 48
WIFI_D2: R6002.2 RP6000.5 ; also on sheet 11 47 48
WIFI_D3: R6003.2 RP6000.6 ; also on sheet 11 47 48
WIFI_HOST_WAKE: R6010.2 U6000.13(WL_HOST_WAKE) ; also on sheet 11 47 48
WIFI_REG_ON: U6000.12(WL_REG_ON) ; also on sheet 11 47 48
XTAL_IN: C6007.2 R6006.1 U6001.3(IN_A2) Y6000.3(XOUT)
XTAL_OUT: C6006.2 R6007.1 Y6000.1(XIN)
N59747349: R6006.2 R6007.2 U6001.1(IN_A1) U6001.4(OUT_Y2)
N59748738: C6012.2 L6000.2 U6000.23(VIN_LDO)
N59748784: C6000.2 C6002.2 U6000.2(WL_BT_ANT)
N59748808: C6000.1 C6003.1 J6000.1(ANT)
N59749115: L6000.1 U6000.21(VIN_LDO_OUT)
N60843264: ED8106.1 J8100.1(DATA2) R8100.2
N60843265: ED8100.1 J8100.9(CD) R8106.2
N60843266: ED8102.1 J8100.7(DATA0) R8104.2
N60843268: ED8104.1 J8100.3(CMD) R8102.2
N60843272: ED8101.1 J8100.8(DATA1) R8105.2
N60843274: ED8105.1 J8100.2(CD/DATA3) R8101.2
N60843277: ED8103.1 J8100.5(CLK) R8103.2
N60851416: C8010.2 U8004.21(CAP)
N60852821: R8000.1 U8000.4(SET)
N60859459: R1502.2 SW1501.3 SW1501.4 T1501.1
N60859537: R1501.2 SW1500.3 SW1500.4 T1500.1
N60861448: D8000.2(K) M8000.1(+) R8007.2
N60861458: D8000.1(A) M8000.2(-) Q8000.3(DRAIN)
N60861466: Q8000.1(GATE) R8010.1
N60914132: C7237.2 ED7206.1 FB7201.2 J7201.1
N60914140: C7239.1 ED7207.1 FB7203.2 J7201.2
N60924389: C7227.2 R7217.2 R7218.2
N60953955: C7603.2 U7600.15(C3P)
N60953959: C7603.1 U7600.14(C3M)
N60953972: C7606.1 U7600.5(VCC)
N60953974: C7608.1 U7600.16(VINT2)
N60953976: C7609.1 U7600.17(VINT3)
N60953978: C7601.2 U7600.10(C1P)
N60953982: C7601.1 U7600.9(C1M)
N60953998: C7602.2 U7600.13(C2P)
N60954006: C7607.1 U7600.11(VINT1)
N60954061: C7602.1 U7600.12(C2M)
N60967858: C8017.1 U8005.10(REGOUT)
N60967882: C8018.2 U8005.20(CPOUT)
N60968857: C8003.2 R8001.2 R8003.1
N60968967: C8001.1 R8002.1 U8002.15(NC)
N60969030: R8004.1 U8002.9(INT2)
N60969036: R8003.2 U8002.3(NC)
N61214880: R1400.2 U1000.D21(OTG_EXTR)
N61292740: C7240.1 ED7209.1 FB7204.2 J7202.2
N61292742: C7238.2 ED7208.1 FB7202.2 J7202.1
N61744935: C8401.1 U8400.4(BP)
N61744941: Q8400.3(C) R8400.1 U8400.3(EN)
N61744945: Q8400.1(B) R8401.2
N61838265: C7702.1 U7700.62(VDD5)
N61840762: C7701.1 U7700.40(VDDD)
N61877408: C8003.1 U8002.2(BYP)
N62019823: C7209.1 U7200.6(IN1N/DMIC2_DAT/JD1)
N62019834: C7208.1 U7200.5(IN1P/DMIC1_DAT)
N62019845: R7204.2 R7205.2 U7200.35(LRCLK1)
N62019865: C7211.1 U7200.8(IN2N/JD2)
N62019868: C7210.1 U7200.7(IN2P)
N62019884: R7202.2 U7200.37(MCLK)
N62019890: R7203.2 U7200.36(BCLK1)
N62019894: C7218.1 U7200.12(VREF2)
N62019940: C7207.2 U7200.27(CPVEE)
N62020011: R7206.2 U7200.33(DACDAT1)
N62020035: C7203.2 U7200.19(CPP2)
N62020063: C7212.1 U7200.11(VREF1)
N62020083: R7207.2 U7200.34(ADCDAT1)
N62020085: C7203.1 U7200.18(CPN2)
N62020150: R7214.1 U7200.32(ADCDAT2)
N62020152: R7213.1 U7200.31(DACDAT2)
N62020158: C7205.2 U7200.20(CPP1)
N62020171: R7212.1 U7200.29(LRCLK2)
N62020173: R7210.1 U7200.30(BLCK2)
N62020225: C7205.1 U7200.21(CPN1)
N62020269: C7206.2 U7200.24(CPVPP)
N62026264: C7234.2 R7227.2
N62026271: ED7204.1 J7200.3 R7221.1
N62026273: C7233.2 R7226.2
N62026316: ED7203.1 J7200.4 R7223.1
N62026366: ED7200.1 J7200.5 R7224.1
N62817989: R1401.2 U1000.C21(HOST2_EXTR)
N62842667: C7225.1 U7201.4(BP)

Not connected (* = marked no-connect by the designer): J7200 6* 7*; J7500 2(NC)* 3(NC)* 4(NC)* 5(NC)*; J7800 1(NC)* 2(NC)* 3(NC)*; J8200 17*; U1000 A23(HOST1_DM)* A27(HSIC_DATA)* B23(HOST1_DP)* B27(HSIC_STROBE)* C23(HOST1_EXTR)* P24(ADC_IN0)*; U6000 4(FM_RX)* 5(N_WAKE)* 8(BT_VIO/N_HOST_WAKE)* 10(XTAL_IN)* 11(XTAL_OUT)* 32(GPS_RF)* 35(N_I2C_SDA)* 37(N_I2C_SCL)* 38(N_REG_PU)* 39(TX2)* 40(TX1)* 45(N_VDDSWPIO)* 46(N_VDDSWP_OUT)* 47(N_VDDSWP_IN)*; U7200 40(GIPO/IRQ)* 41(DMIC_SCL)*; U7600 1(TP_Sync)*; U7700 26(TX31)* 27(TX32)* 44(MISO)*; U7800 1(Y18)* 2(Y19)* 4(X30)* 20(VDDCORE)* 23(I2C_ADD)* 24(GPIO0/RXD)* 25(GPIO0/TXD)* 29(VTNC)* 42(X12)* 43(X13)* 44(X14)* 45(X15)* 63(Y16)* 64(Y17)*; U8001 B3(RSV)* B4(SO)* C2(TST1)* C3(TRG)*; U8004 9(DRDY_G/INT2_G)* 12(INT2_A)* 13(DEN_G)*; U8005 2(NC#1)* 3(NC#2)* 4(NC#3)* 5(NC#4)* 6(AUX_DA)* 7(AUX_CL)* 14(NC#5)* 15(NC#6)* 16(NC#7)* 17(NC#8)* 19(RESV1)* 21(RESV)* 22(CLKOUT)*

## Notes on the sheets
sheet 35
- CODEC
- MIC
- EARPHONE
- SPEAKER
sheet 36
- Touch Panel connector
sheet 37
- Touch IC
- note：CT363 suit for Touch Panel Size≤10.1''。
sheet 38
- Touch IC
- note：FT5506 suit for Touch Panel Size≤9.0''。
        Download firmware use the Reset Pin
sheet 39
- Touch IC
- note：GSL3680B suit for Touch Panel Size≤10.1''。
sheet 40
- TF CARD
sheet 41
- HDMI
sheet 42
- EFUSE Power
- Note:Place the Component if need to write eFUSE
sheet 43
- G-sensor
- Compass
- LIGHT-Sensor
- LSM303D with 3D Gsensor and E-compass
- Note:
  The first pin of AK8963C must be
  place on the lower left corner of
  PCB.
- LIS3DH
- MMA8452Q
- LSM303D
- C8004
- R8003
- 0ohm
- NC
- NC
- NC
- 4.7uF
- NC
- R8001
- NC
- 0ohm
- NC
- C8001
- NC
- 0.1uF
- 0.22uF
- R8002
- NC
- NC
- 0R
- R8004
- NC
- NC
- 0R
- Hall-Sensor
- Gyroscope+G-sensor
- VIBRATION
- OPTION1
- OPTION2
sheet 44
- WIFI/BT MODULE
- Note:VBAT电压范围3.0V~4.8V，
       供电电流至少400mA
- 50 Ohm RF trace
- up to 700mA
sheet 45
- KEY BAORD
